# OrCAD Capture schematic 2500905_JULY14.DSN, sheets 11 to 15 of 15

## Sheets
11 PAGE5: size Custom
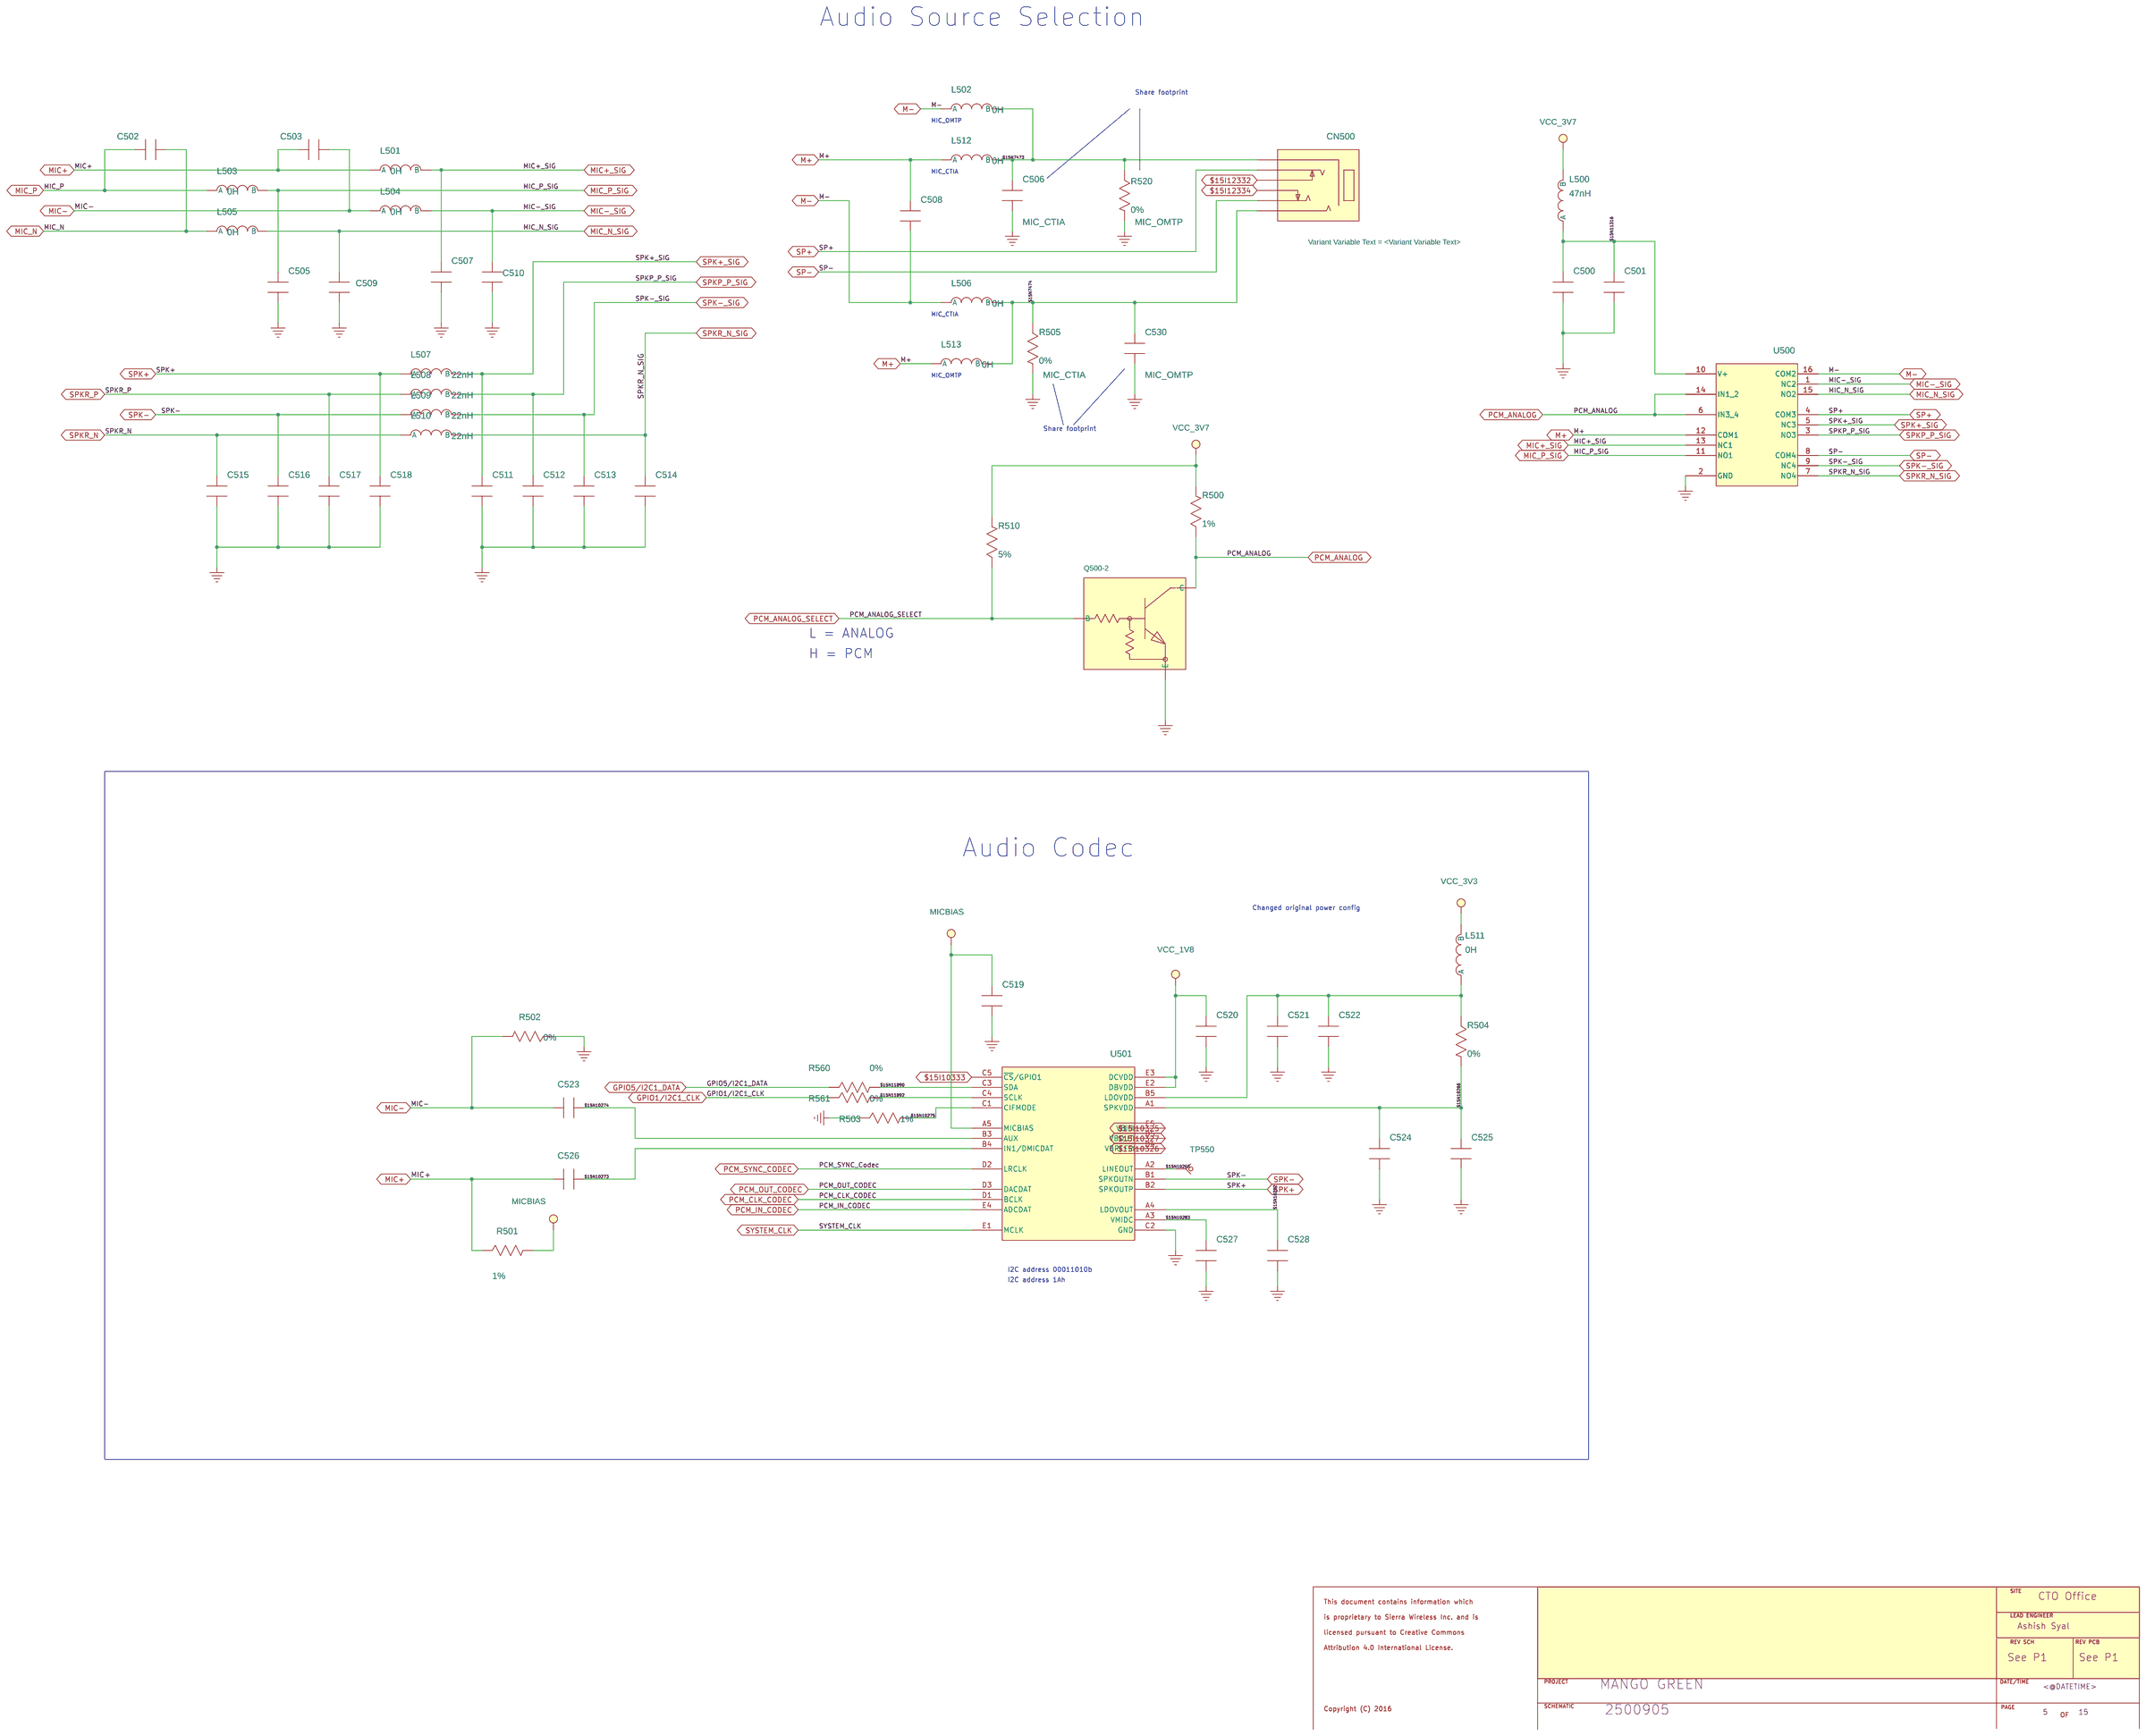
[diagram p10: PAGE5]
12 PAGE4: size Custom
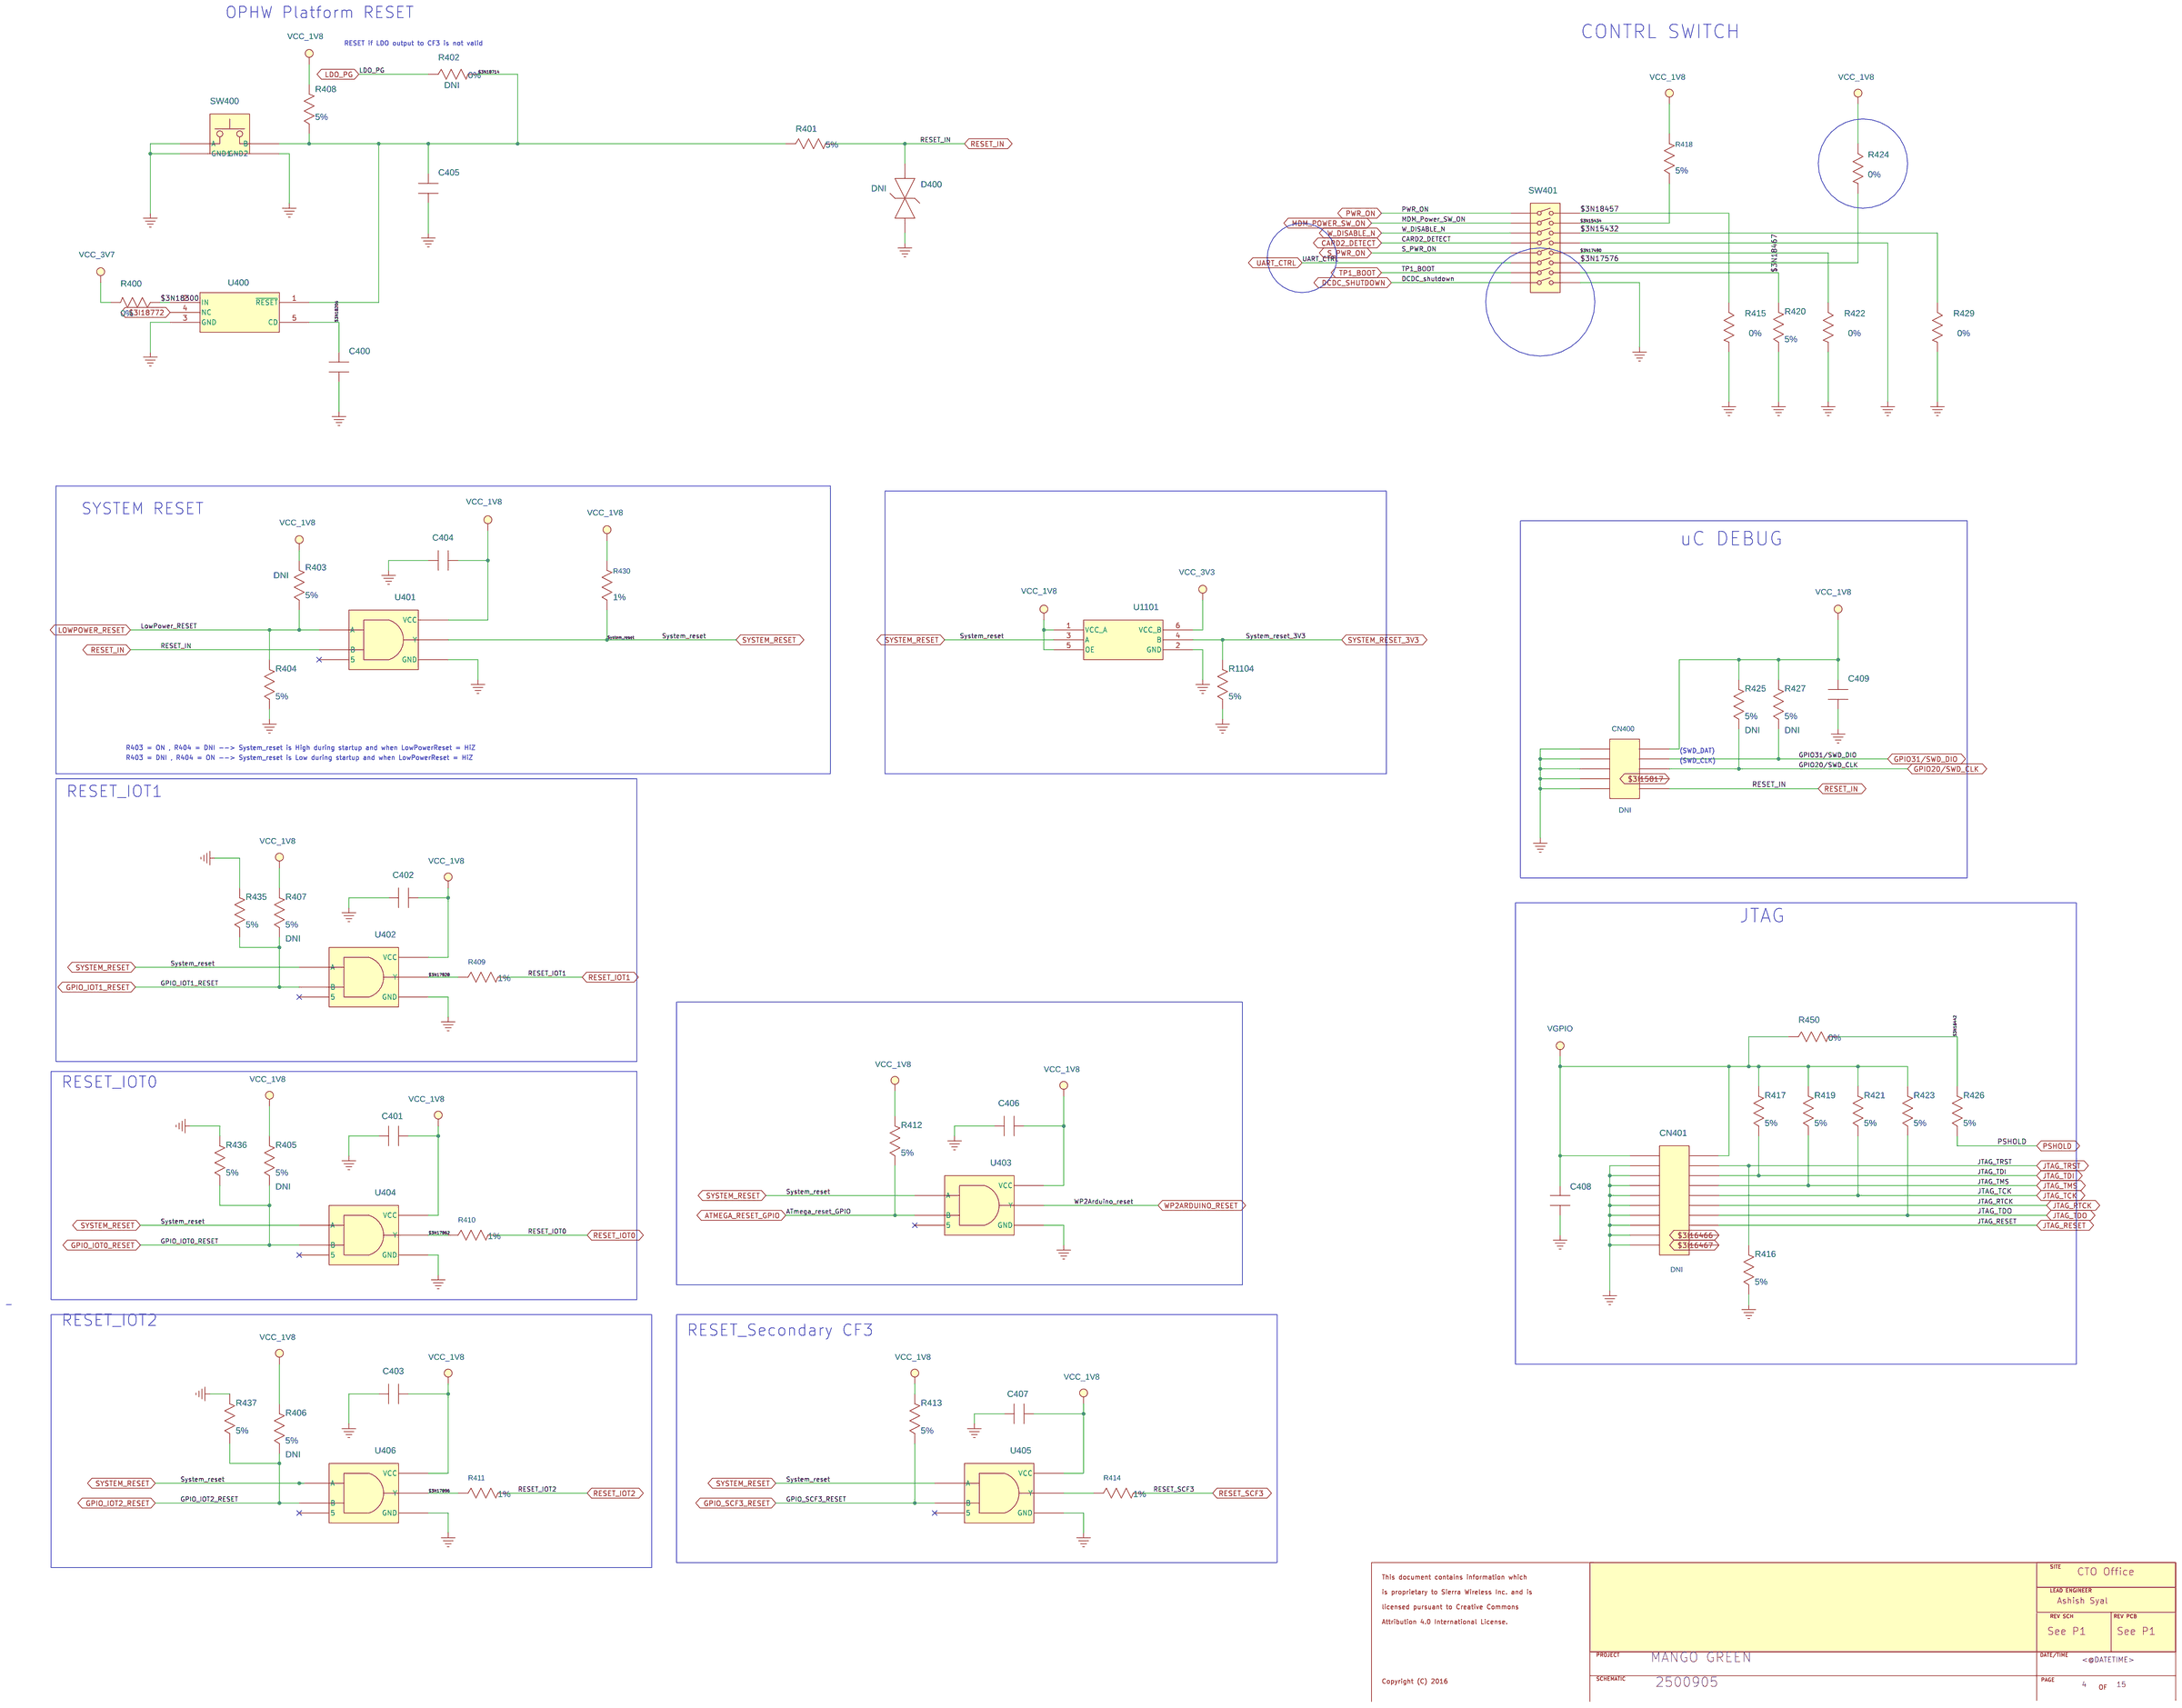
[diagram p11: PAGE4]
13 PAGE3: size Custom
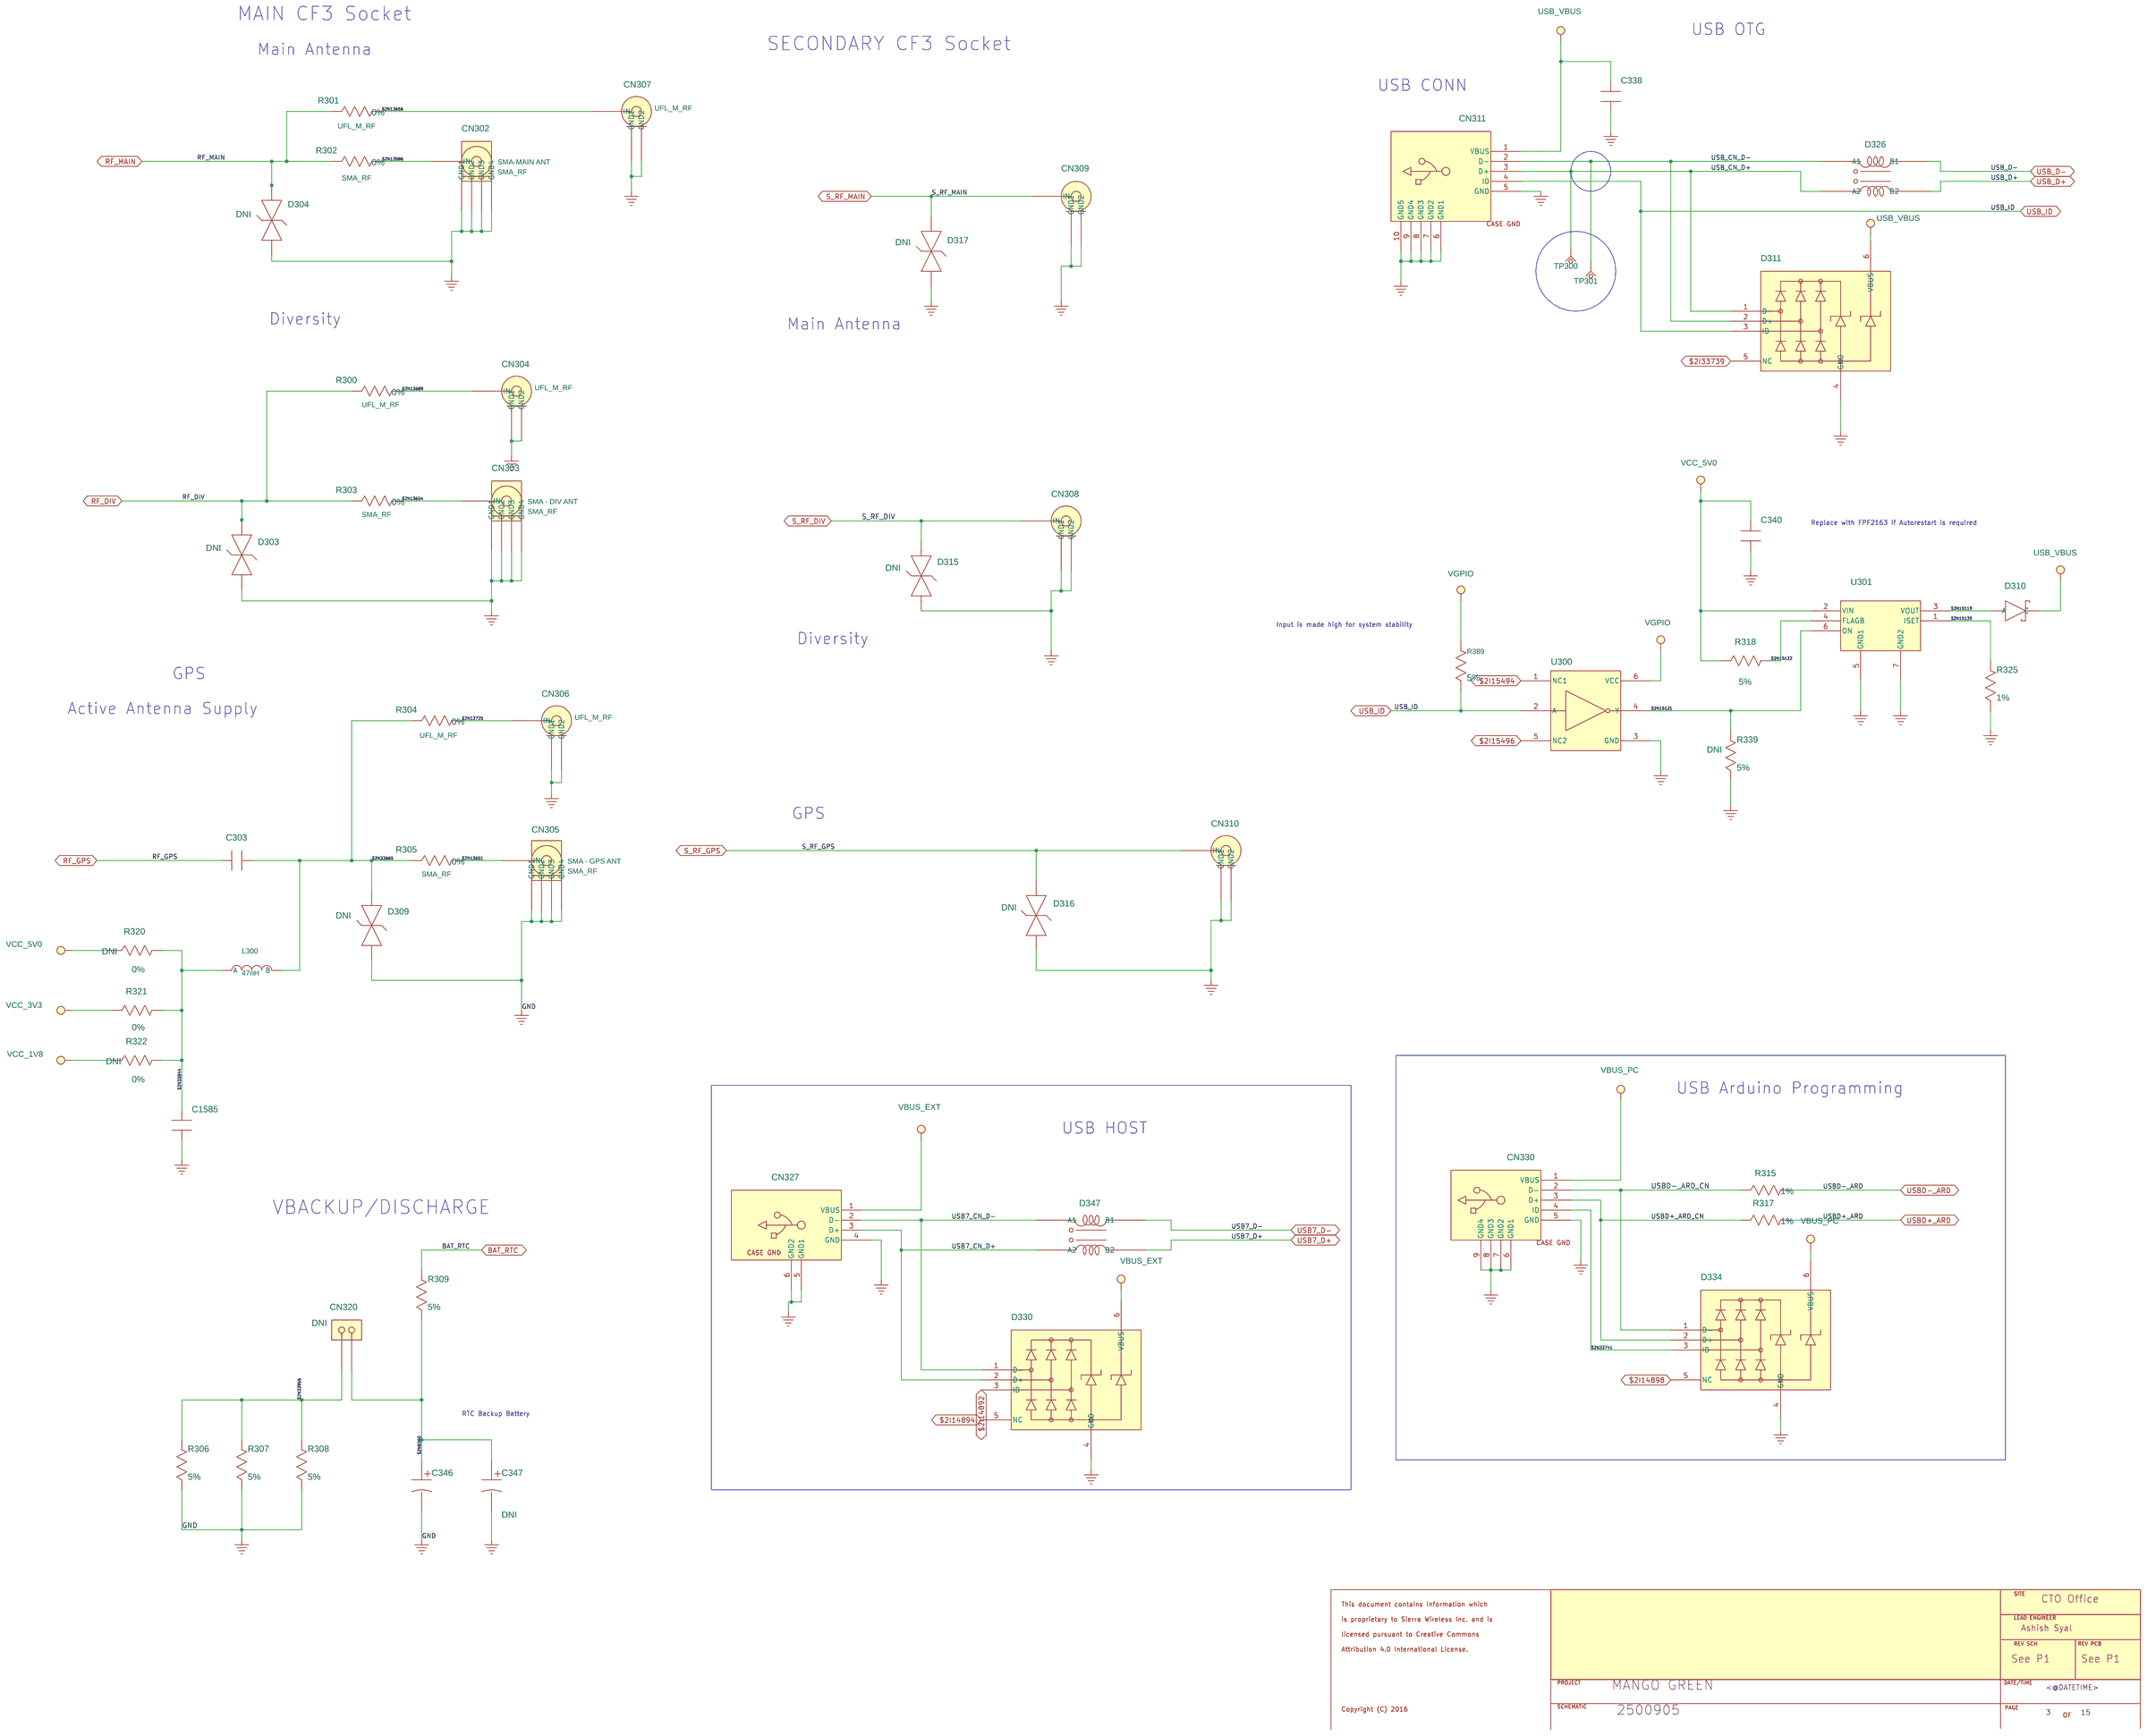
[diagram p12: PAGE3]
14 PAGE2: size Custom
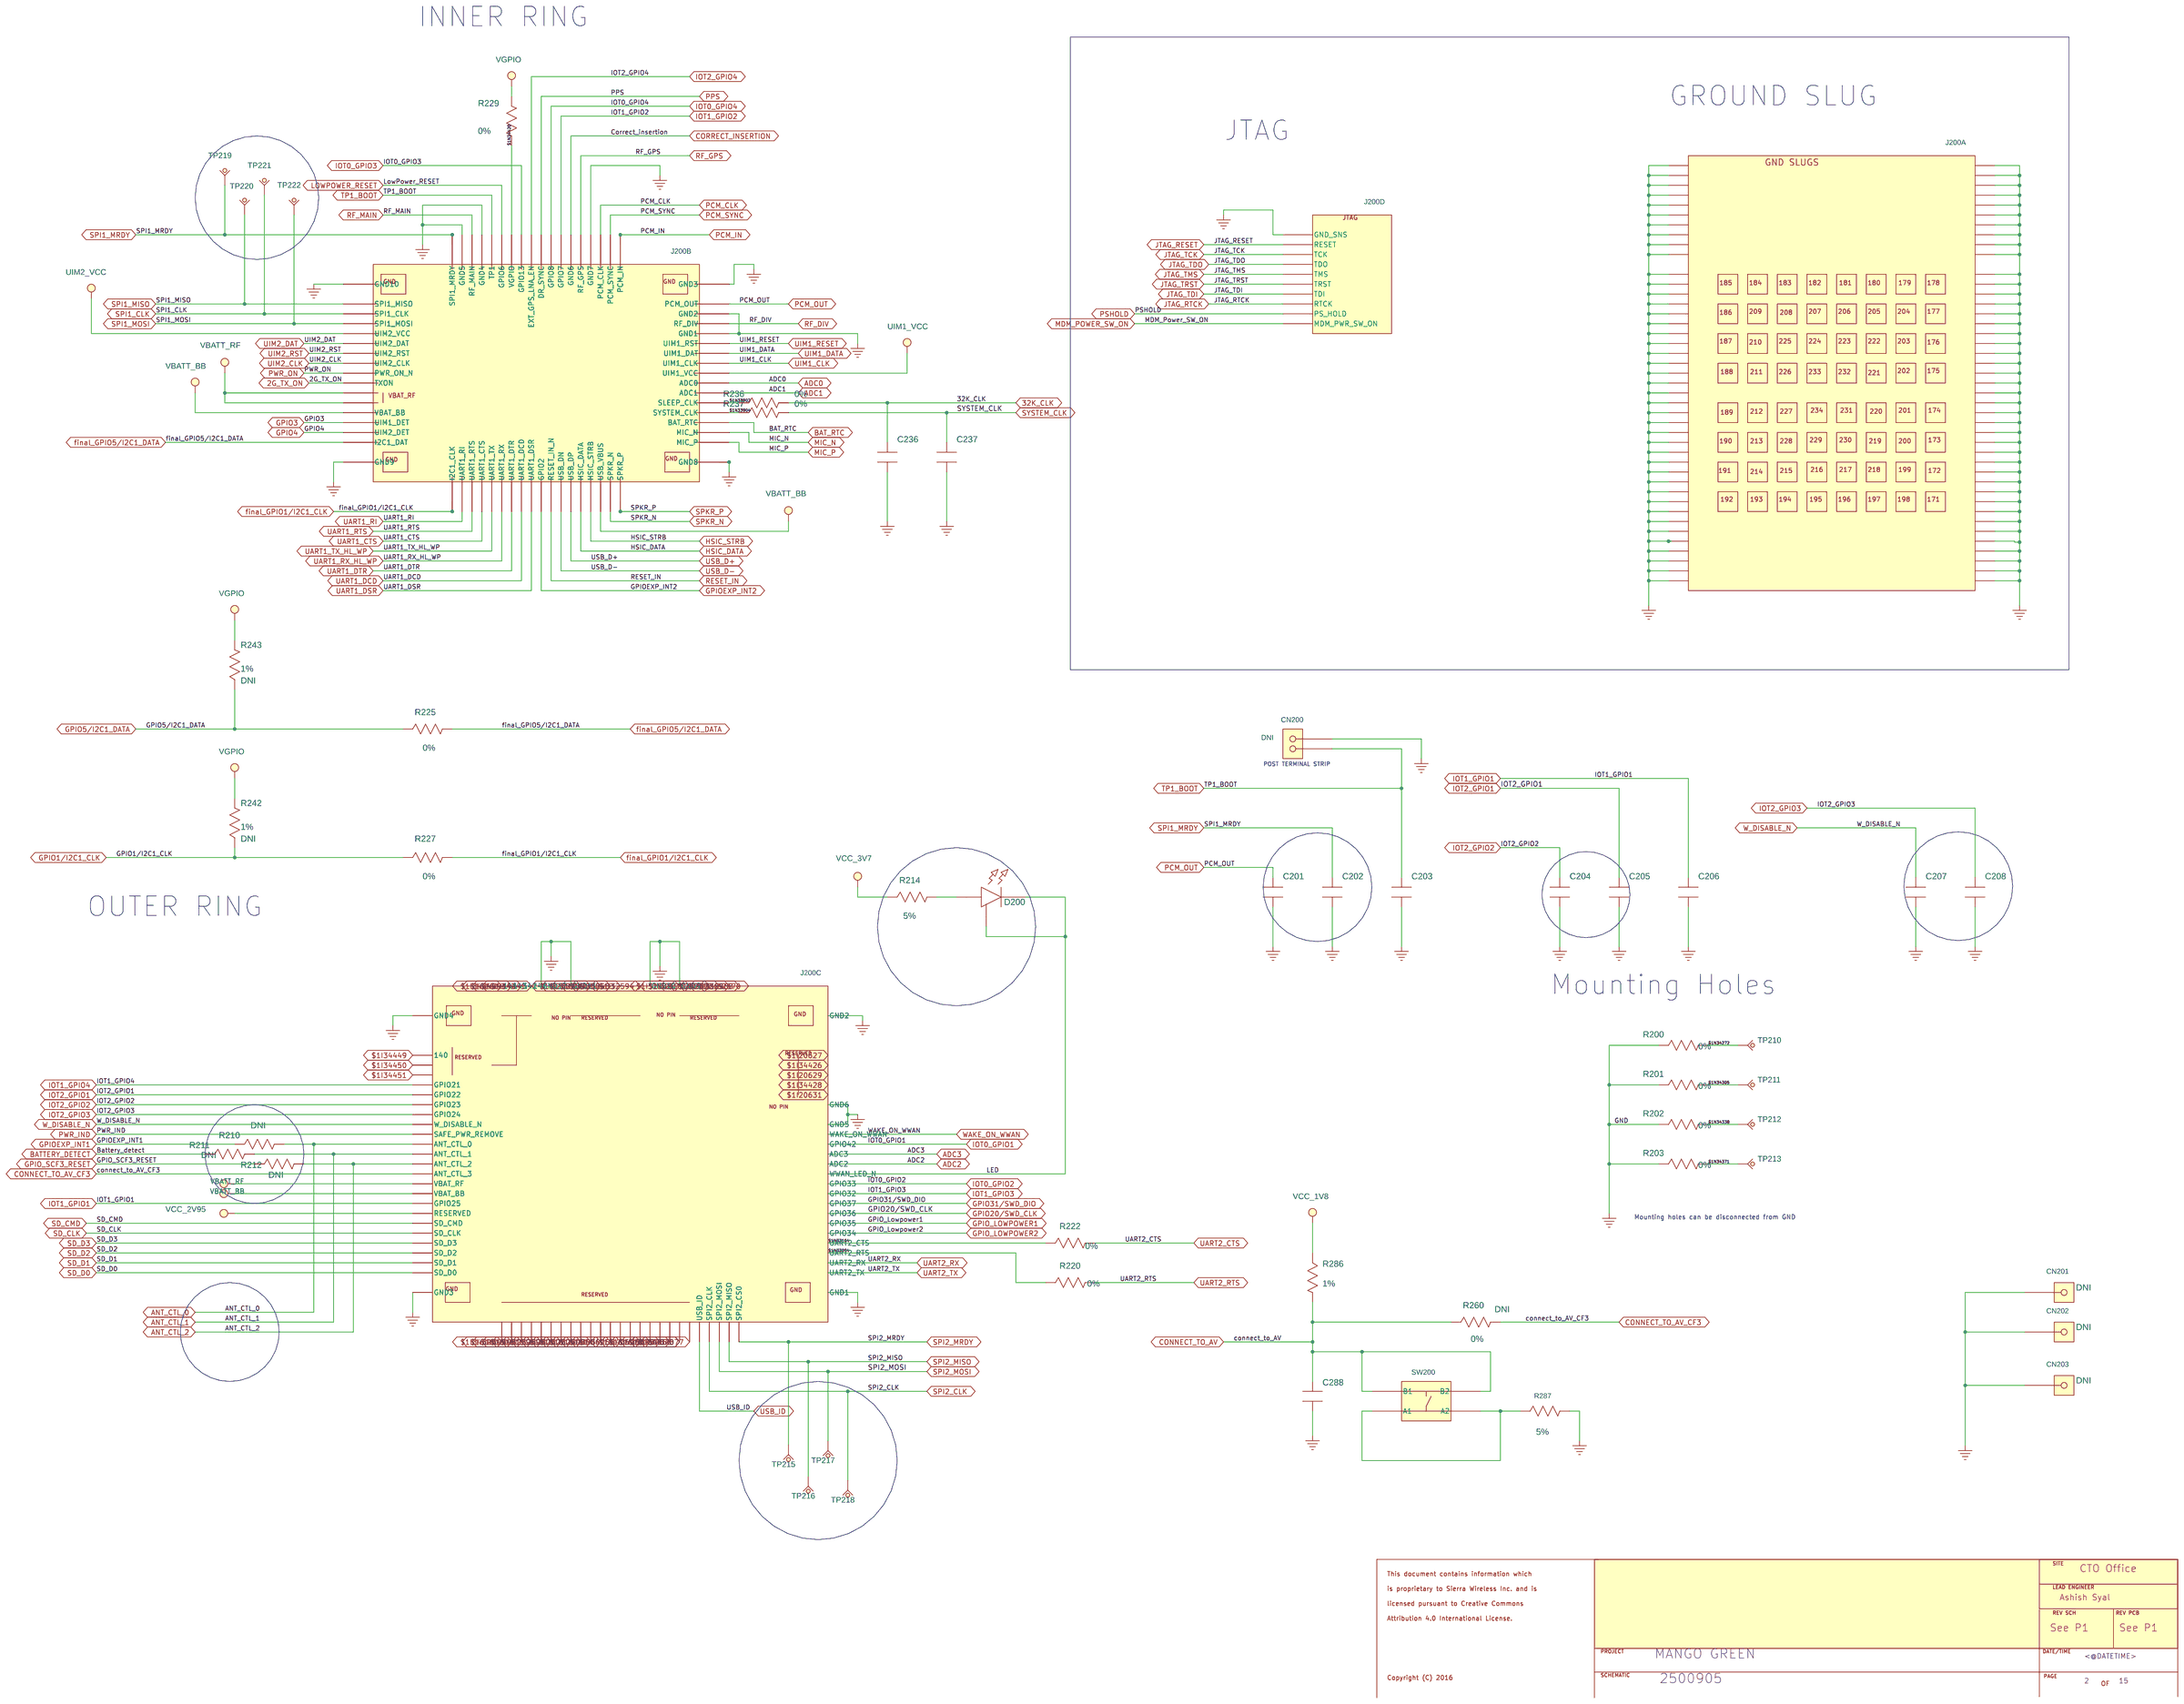
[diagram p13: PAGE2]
15 PAGE1
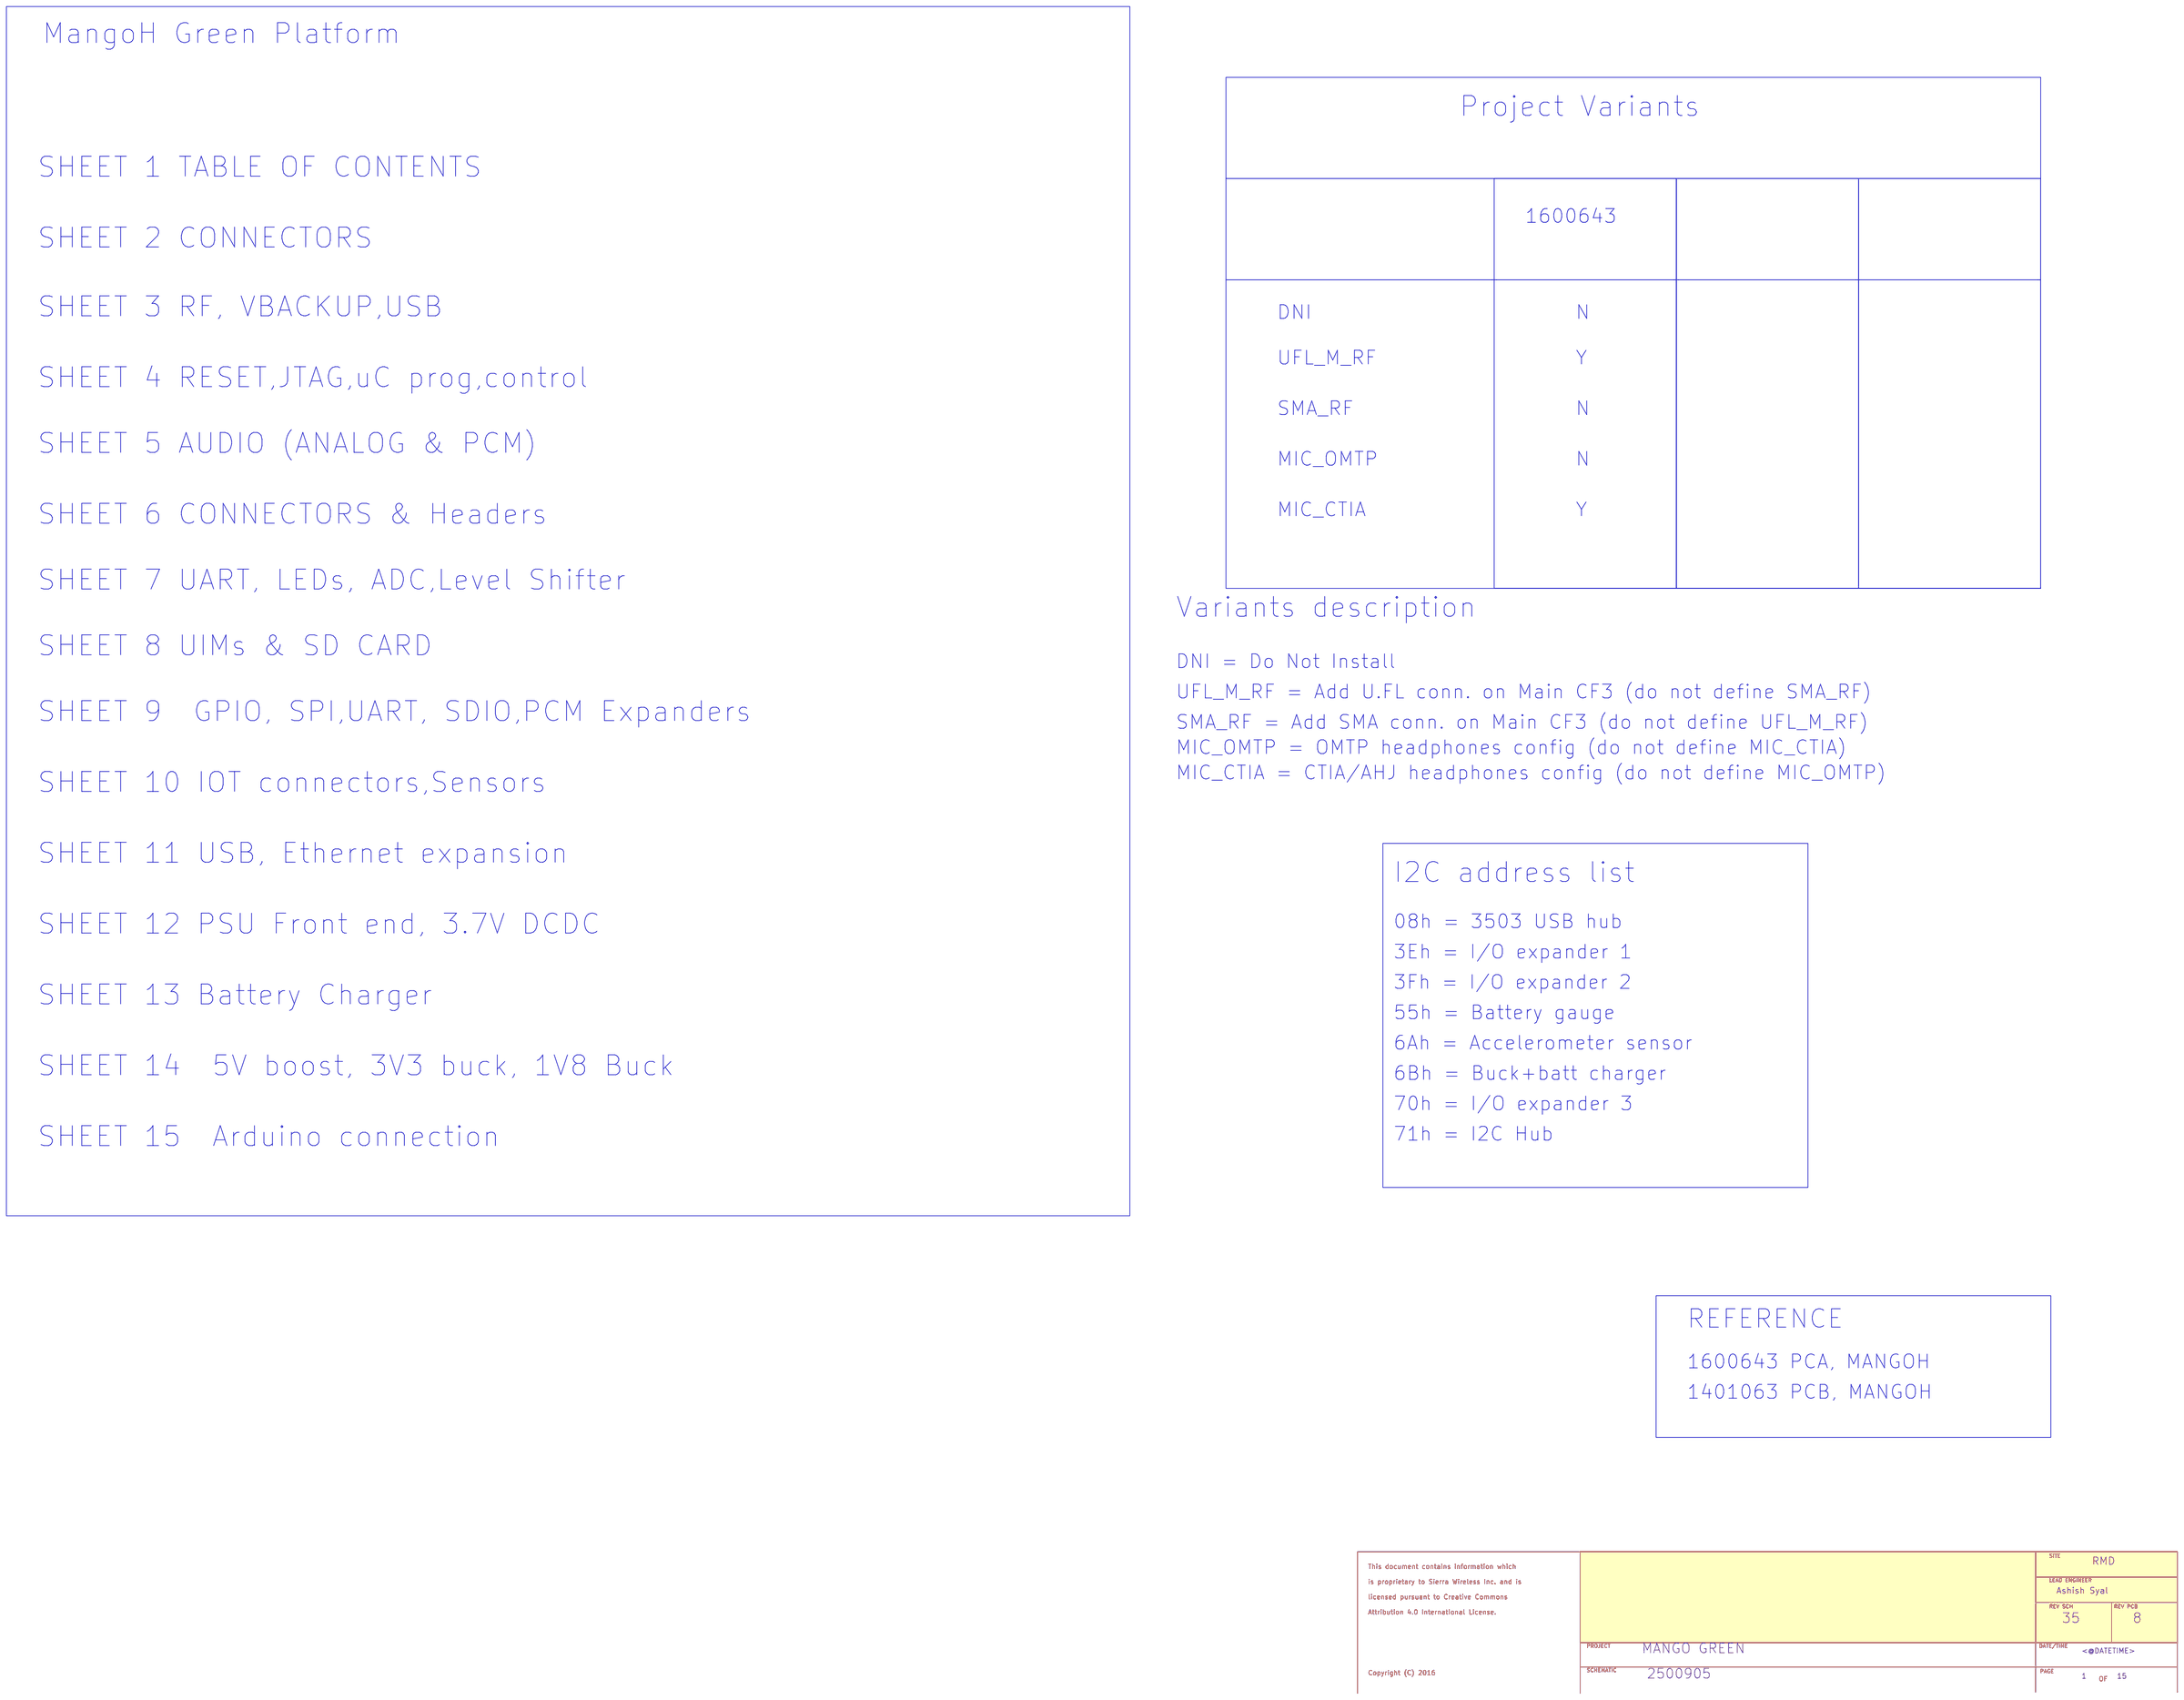
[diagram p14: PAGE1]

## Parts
sheet PAGE1
1  C_OPEN_HW  [TP]
sheet PAGE2
2  C_OPEN_HW  [TP]
C201  22pF  [0402C]
C202  22pF  [0402C]
C203  22pF  [0402C]
C204  22pF  [0402C]
C205  22pF  [0402C]
C206  22pF  [0402C]
C207  22pF  [0402C]
C208  22pF  [0402C]
C236  12pF  [0402C]
C237  12pF  [0402C]
C288  100nF  [0402C]
CN200  CN_2P_SINGLE_ROW  [CONN_2P_0508x0254_VERTICAL_HEADER_SINGLE_ROW_THRU_SAMTEC_TSW]
CN201  CN_1P_SINGLE_ROW  [TP_THRU_0235_RND_0160D]
CN202  CN_1P_SINGLE_ROW  [TP_THRU_0235_RND_0160D]
CN203  CN_1P_SINGLE_ROW  [TP_THRU_0235_RND_0160D]
D200  LED GREEN  [LED_3P_0300x0200_RA]
J200  MULTI_SYMBOL_SOCKET_LGA-244  [LGA_244P_CF3_2650x2550_SNAP_IN_SOCKET_SMK]  (sections A,B,C,D)
R200  0  [0402R]
R201  0  [0402R]
R202  0  [0402R]
R203  0  [0402R]
R210  0  [0402R]
R211  0  [0402R]
R212  0  [0402R]
R214  1.5K  [0402R]
R220  0  [0402R]
R222  0  [0402R]
R225  0  [0402R]
R227  0  [0402R]
R229  0  [0402R]
R236  0  [0402R]
R237  0  [0402R]
R242  2.2K  [0402R]
R243  2.2K  [0402R]
R260  0  [0402R]
R286  10K  [0402R]
R287  100  [0402R]
SW200  SW_4P_PTS810 SJK 250 SMTR LFS  [SW_4P_0420x0320_0215CC]
TP210  TESTPOINT_0650_RND_0350H  [TP_0650_RND_0350H_NP]
TP211  TESTPOINT_0650_RND_0350H  [TP_0650_RND_0350H_NP]
TP212  TESTPOINT_0650_RND_0350H  [TP_0650_RND_0350H_NP]
TP213  TESTPOINT_0650_RND_0350H  [TP_0650_RND_0350H_NP]
TP215  TESTPOINT_0100_RND  [TP_0100_RND_NP]
TP216  TESTPOINT_0100_RND  [TP_0100_RND_NP]
TP217  TESTPOINT_0100_RND  [TP_0100_RND_NP]
TP218  TESTPOINT_0100_RND  [TP_0100_RND_NP]
TP219  TESTPOINT_0100_RND  [TP_0100_RND_NP]
TP220  TESTPOINT_0100_RND  [TP_0100_RND_NP]
TP221  TESTPOINT_0100_RND  [TP_0100_RND_NP]
TP222  TESTPOINT_0100_RND  [TP_0100_RND_NP]
sheet PAGE3
3  C_OPEN_HW  [TP]
C303  15pF  [0402C]
C338  10uF  [0603C]
C340  10uF  [0603C]
C346  1.5mF  [CAP_2P_0720x0630_POL_NIB]
C347  1.5mF  [CAP_2P_0720x0630_POL_NIB]
C1585  22pF  [0402C]
CN302  SMA  [CONN_5P_0955x1430_RA_EDGE_MOUNT_RF_SMA]
CN303  SMA  [CONN_5P_0955x1430_RA_EDGE_MOUNT_RF_SMA]
CN304  CN_3P_RF_GENERIC  [CONN_3P_0300x0310_RF_HIROSE]
CN305  SMA  [CONN_5P_0955x1430_RA_EDGE_MOUNT_RF_SMA]
CN306  CN_3P_RF_GENERIC  [CONN_3P_0300x0310_RF_HIROSE]
CN307  CN_3P_RF_GENERIC  [CONN_3P_0300x0310_RF_HIROSE]
CN308  CN_3P_RF_GENERIC  [CONN_3P_0300x0310_RF_HIROSE]
CN309  CN_3P_RF_GENERIC  [CONN_3P_0300x0310_RF_HIROSE]
CN310  CN_3P_RF_GENERIC  [CONN_3P_0300x0310_RF_HIROSE]
CN311  CN_5P_USB_5P_GND  [CONN_5P_0750x0560_USB_5GND_HRS_ZX62RD]
CN320  POST TERMINAL STRIP  [CONN_2P_0508x0254_VERTICAL_HEADER_SINGLE_ROW_THRU_SAMTEC_TSW]
CN327  CN_4P_USB_2P_GND  [CONN_4P_1450x1400_USB_2GND_RA_THRU]
CN330  USB CONN  [CONN_5P_0770x0900_USB_4GND_SMK_CSS5005-0401]
D303  0.05pF  [0402E]
D304  0.05pF  [0402E]
D309  0.05pF  [0402E]
D310  DIODE_SCHOTTKY  [DIO_2P_0270x0165_SOD123]
D311  DIODE_6P_ESD_TPD4S012DRYR  [DFN_6P_0145x0100_0050CC]
D315  0.05pF  [0402E]
D316  0.05pF  [0402E]
D317  0.05pF  [0402E]
D326  0H  [IND_4P_0100x0125_0055CC]
D330  DIODE_6P_ESD_TPD4S012DRYR  [DFN_6P_0145x0100_0050CC]
D334  DIODE_6P_ESD_TPD4S012DRYR  [DFN_6P_0145x0100_0050CC]
D347  0H  [IND_4P_0100x0125_0055CC]
L300  47nH  [0402L]
R300  0  [0402R]
R301  0  [0402R]
R302  0  [0402R]
R303  0  [0402R]
R304  0  [0402R]
R305  0  [0402R]
R306  300  [0402R]
R307  300  [0402R]
R308  300  [0402R]
R309  10K  [0402R]
R315  22  [0402R]
R317  22  [0402R]
R318  51K  [0402R]
R320  0  [0402R]
R321  0  [0402R]
R322  0  [0402R]
R325  470  [0402R]
R339  51K  [0402R]
R389  51K  [0402R]
TP300  TESTPOINT_0100_RND  [TP_0100_RND_NP]
TP301  TESTPOINT_0100_RND  [TP_0100_RND_NP]
U300  SN74LVC1G04DRYRG4  [DFN_6P_0145x0100_0050CC]
U301  FPF2164  [DFN_6P_0200x0200_SLUG_0140x0080_0065CC]
sheet PAGE4
4  C_OPEN_HW  [TP]
C400  100nF  [0402C]
C401  100nF  [0402C]
C402  100nF  [0402C]
C403  100nF  [0402C]
C404  100nF  [0402C]
C405  100nF  [0402C]
C406  100nF  [0402C]
C407  100nF  [0402C]
C408  100nF  [0402C]
C409  100nF  [0402C]
CN400  SFMC-105-02-L-D-TR  [CONN_10P_0673x0305_0127CC_SMT]
CN401  SFMC-110-02-L-D-TR  [CONN_20P_1308x0305_0127CC_SMT]
D400  0.05pF  [0402E]
R400  0  [0402R]
R401  100  [0402R]
R402  0  [0402R]
R403  47K  [0402R]
R404  47K  [0402R]
R405  47K  [0402R]
R406  47K  [0402R]
R407  47K  [0402R]
R408  47K  [0402R]
R409  330  [0402R]
R410  330  [0402R]
R411  330  [0402R]
R412  47K  [0402R]
R413  47K  [0402R]
R414  330  [0402R]
R415  0  [0402R]
R416  10K  [0402R]
R417  10K  [0402R]
R418  10K  [0402R]
R419  10K  [0402R]
R420  10K  [0402R]
R421  10K  [0402R]
R422  0  [0402R]
R423  10K  [0402R]
R424  0  [0402R]
R425  10K  [0402R]
R426  10K  [0402R]
R427  10K  [0402R]
R429  0  [0402R]
R430  10K  [0402R]
R435  47K  [0402R]
R436  47K  [0402R]
R437  47K  [0402R]
R450  0  [0402R]
R1104  47K  [0402R]
SW400  SW_4P_T6HA-25GQB  [SW_4P_0850x0600_RT_ANGLE_SPST]
SW401  1-1571983-1  [SW_16P_1128x0620_0127CC_DIP_SPST]
U400  NCP303LSN30T1G  [SOT23_5P_0300x0160_0095CC]
U401  IC_5P_AND_GATE_2_INPUT_GENERI  [DFN_6P_0145x0100_0050CC]
U402  IC_5P_AND_GATE_2_INPUT_GENERI  [DFN_6P_0145x0100_0050CC]
U403  IC_5P_AND_GATE_2_INPUT_GENERI  [DFN_6P_0145x0100_0050CC]
U404  IC_5P_AND_GATE_2_INPUT_GENERI  [DFN_6P_0145x0100_0050CC]
U405  IC_5P_AND_GATE_2_INPUT_GENERI  [DFN_6P_0145x0100_0050CC]
U406  IC_5P_AND_GATE_2_INPUT_GENERI  [DFN_6P_0145x0100_0050CC]
U1101  IC_6P_NTB0101GW  [SC88_6P_0210x0125_0065CC]
sheet PAGE5
5  C_OPEN_HW  [TP]
C500  22pF  [0402C]
C501  100nF  [0402C]
C502  100pF  [0402C]
C503  100pF  [0402C]
C505  100pF  [0402C]
C506  100pF  [0402C]
C507  100pF  [0402C]
C508  100pF  [0402C]
C509  100pF  [0402C]
C510  100pF  [0402C]
C511  22pF  [0402C]
C512  22pF  [0402C]
C513  22pF  [0402C]
C514  22pF  [0402C]
C515  100pF  [0402C]
C516  100pF  [0402C]
C517  100pF  [0402C]
C518  100pF  [0402C]
C519  4.7uF  [0402C]
C520  4.7uF  [0402C]
C521  4.7uF  [0402C]
C522  100nF  [0402C]
C523  1uF  [0402C]
C524  100nF  [0402C]
C525  4.7uF  [0402C]
C526  1uF  [0402C]
C527  4.7uF  [0402C]
C528  2.2uF  [0603C]
C530  100pF  [0402C]
CN500  3.5MM AUDIO JACK  [CONN_6P_1480x0640_AUDIO_JACK_DUAL]
L500  47nH  [0402L]
L501  0H  [0402L]
L502  0H  [0402L]
L503  0H  [0402L]
L504  0H  [0402L]
L505  0H  [0402L]
L506  0H  [0402L]
L507  22nH  [0402L]
L508  22nH  [0402L]
L509  22nH  [0402L]
L510  22nH  [0402L]
L511  0H  [0603L]
L512  0H  [0402L]
L513  0H  [0402L]
Q500  NSBC114YDP6T5G  [SOT963_6P_0100x0080_0035CC]  (section -2)
R500  1K  [0402R]
R501  2.2K  [0402R]
R502  0  [0402R]
R503  20K  [0402R]
R504  0  [0402R]
R505  0  [0402R]
R510  10K  [0402R]
R520  0  [0402R]
R560  0  [0402R]
R561  0  [0402R]
TP550  TESTPOINT_0035_RND  [TP_0035_RND_NP]
U500  TS3A44159RSVR  [QFN_16P_0260x0180_0040CC]
U501  WM8944BECS/R  [BGA_25P_0241x0241_0050CC_0030PD]

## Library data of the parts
1 = Sierra_Title_Block_0: @DATETIME: <@DATETIME>; @Name: 2500905; @SheetTotal: 15; AUTHOR: Ashish Syal; PROJECT: MANGO GREEN; REVISION_PCB: 8; REVISION_SCH: 35; SITE: RMD
2-5 = Sierra_Title_Block_0: @DATETIME: <@DATETIME>; @Name: 2500905; @SheetTotal: 15; AUTHOR: Ashish Syal; PROJECT: MANGO GREEN; REVISION_PCB: See P1; REVISION_SCH: See P1; SITE: CTO Office
C201-C208 C500 C511-C514 C1585 = CAP_GRM1555C1H220JA01D: ASSEMBLY: <ASSEMBLY>; Variant Variable Text: <Variant Variable Text>
C236 C237 = CAP_GRM1555C1H120JA01D: ASSEMBLY: <ASSEMBLY>; Variant Variable Text: <Variant Variable Text>
C288 C400-C409 C501 C522 C524 = CAP_NMC0402X7R104K16TRPF: ASSEMBLY: <ASSEMBLY>; Variant Variable Text: <Variant Variable Text>
CN200 CN320 = CN_2P_SINGLE_ROW: ASSEMBLY: <ASSEMBLY>; Variant Variable Text: DNI
CN201-CN203 = CN_1P_SINGLE_ROW: ASSEMBLY: <ASSEMBLY>; Variant Variable Text: DNI
D200 = LED_3P: ASSEMBLY: <ASSEMBLY>; Variant Variable Text: <Variant Variable Text>
J200 = MULTI_SYMBOL_SOCKET_LGA-244_0: ASSEMBLY: <ASSEMBLY>; Variant Variable Text: <Variant Variable Text>
R200-R203 R220 R222 R225 R227 R229 R236 R237 R321 R400 R415 R422 R424 R429 R450 R502 R504 R560 R561 = RES_RK73Z1ETTP: ASSEMBLY: <ASSEMBLY>; TOLERANCE: 0%; Variant Variable Text: <Variant Variable Text>
R210-R212 = RES_RK73Z1ETTP: ASSEMBLY: <ASSEMBLY>; TOLERANCE: <TOLERANCE>; Variant Variable Text: DNI
R214 = RES_RK73B1ETTP152J: ASSEMBLY: <ASSEMBLY>; TOLERANCE: 5%; Variant Variable Text: <Variant Variable Text>
R242 R243 = RES_RK73H1ETTP2201F: ASSEMBLY: <ASSEMBLY>; TOLERANCE: 1%; Variant Variable Text: DNI
R260 R320 R322 R402 = RES_RK73Z1ETTP: ASSEMBLY: <ASSEMBLY>; TOLERANCE: 0%; Variant Variable Text: DNI
R286 R430 = RES_MCR01MZPF1002: ASSEMBLY: <ASSEMBLY>; TOLERANCE: 1%; Variant Variable Text: <Variant Variable Text>
R287 R401 = RES_RK73B1ETTP101J_0: ASSEMBLY: <ASSEMBLY>; TOLERANCE: 5%; Variant Variable Text: <Variant Variable Text>
SW200 = SW_4P_PTS810_SJK_250_SMTR_LFS: ASSEMBLY: <ASSEMBLY>; Variant Variable Text: <Variant Variable Text>
TP210-TP213 = TESTPOINT: TEST POINT, ROUND, 6.5mm DIAMETER, 3.5mm DIAMETER HOLE; CATEGORY: Layout Feature; DXDB_LIBNAME: Layout_Feature; OWNER: Chris Ivanciuc; Part Height: 0.01mm; REQUESTOR: Chris Ivanciuc
TP215-TP222 TP300 TP301 = TESTPOINT: TEST POINT, ROUND, 1mm DIAMETER; CATEGORY: Layout Feature; DXDB_LIBNAME: Layout_Feature; OWNER: Michael Sorensen; Part Height: 0.01mm; REQUESTOR: Michael Sorensen
C303 = CAP_GRM1555C1H150JA01D: ASSEMBLY: <ASSEMBLY>; Variant Variable Text: <Variant Variable Text>
C338 C340 = CAP_GRM188R61A106ME69D: ASSEMBLY: <ASSEMBLY>; Variant Variable Text: <Variant Variable Text>
C346 = CAP_POL-592D158X06R3R2T20H: ASSEMBLY: <ASSEMBLY>; Variant Variable Text: <Variant Variable Text>
C347 = CAP_POL-592D158X06R3R2T20H: ASSEMBLY: <ASSEMBLY>; Variant Variable Text: DNI
CN302 = CN_5P_RF_GENERIC: ASSEMBLY: SMA-MAIN ANT; Variant Variable Text: SMA_RF
CN303 = CN_5P_RF_GENERIC: ASSEMBLY: SMA - DIV ANT; Variant Variable Text: SMA_RF
CN304 CN306 CN307 = CN_3P_RF_GENERIC: ASSEMBLY: <ASSEMBLY>; Variant Variable Text: UFL_M_RF
CN305 = CN_5P_RF_GENERIC: ASSEMBLY: SMA - GPS ANT; Variant Variable Text: SMA_RF
CN308-CN310 = CN_3P_RF_GENERIC: ASSEMBLY: <ASSEMBLY>
CN311 = CN_5P_USB_5P_GND_0: ASSEMBLY: <ASSEMBLY>; Variant Variable Text: <Variant Variable Text>
CN327 = CN_4P_USB_2P_GND: ASSEMBLY: <ASSEMBLY>; Variant Variable Text: <Variant Variable Text>
CN330 = CN_5P_USB_4P_GND: ASSEMBLY: <ASSEMBLY>; Variant Variable Text: <Variant Variable Text>
D303 D304 D309 D315-D317 D400 = DIODE_ESD_SUPPRESSOR_0: ASSEMBLY: <ASSEMBLY>; Variant Variable Text: DNI
D310 = DIODE_SCHOTTKY_0: ASSEMBLY: <ASSEMBLY>; Variant Variable Text: <Variant Variable Text>
D311 D330 D334 = DIODE_6P_ESD_TPD4S012DRYR: ASSEMBLY: <ASSEMBLY>; Variant Variable Text: <Variant Variable Text>
D326 D347 = CHOKE_4P_COMMON_MODE_GENERIC: ASSEMBLY: <ASSEMBLY>; Variant Variable Text: <Variant Variable Text>
L300 L500 = IND_LQG15HN47NJ02D_0
R300 R301 R304 = RES_RK73Z1ETTP: ASSEMBLY: <ASSEMBLY>; TOLERANCE: 0%; Variant Variable Text: UFL_M_RF
R302 R303 R305 = RES_RK73Z1ETTP: ASSEMBLY: <ASSEMBLY>; TOLERANCE: 0%; Variant Variable Text: SMA_RF
R306-R308 = RES_RK73B1ETTP301J: ASSEMBLY: <ASSEMBLY>; TOLERANCE: 5%; Variant Variable Text: <Variant Variable Text>
R309 R416-R421 R423 R426 R510 = RES_MCR01MZPJ103: ASSEMBLY: <ASSEMBLY>; TOLERANCE: 5%; Variant Variable Text: <Variant Variable Text>
R315 R317 = RES_RK73H1ETTP22R0F: ASSEMBLY: <ASSEMBLY>; TOLERANCE: 1%; Variant Variable Text: <Variant Variable Text>
R318 R389 = RES_MCR01MZPJ513: ASSEMBLY: <ASSEMBLY>; TOLERANCE: 5%; Variant Variable Text: <Variant Variable Text>
R325 = RES_MCR01MZPF4700: ASSEMBLY: <ASSEMBLY>; TOLERANCE: 1%; Variant Variable Text: <Variant Variable Text>
R339 = RES_MCR01MZPJ513: ASSEMBLY: <ASSEMBLY>; TOLERANCE: 5%; Variant Variable Text: DNI
U300 = IC_6P_INVERTER_GENERIC: ASSEMBLY: <ASSEMBLY>; Variant Variable Text: <Variant Variable Text>
U301 = IC_6P_LOAD_SWITCH_FPF2164: ASSEMBLY: <ASSEMBLY>; Variant Variable Text: <Variant Variable Text>
CN400 = CN_10P_DUAL_ROW_Z_NO_BUBBLES: ASSEMBLY: <ASSEMBLY>; Variant Variable Text: DNI
CN401 = CN_20P_DUAL_ROW_Z_NO_BUBBLES: ASSEMBLY: <ASSEMBLY>; Variant Variable Text: DNI
R403 R405-R407 = RES_MCR01MZPJ473: ASSEMBLY: <ASSEMBLY>; TOLERANCE: 5%; Variant Variable Text: DNI
R404 R408 R412 R413 R435-R437 R1104 = RES_MCR01MZPJ473: ASSEMBLY: <ASSEMBLY>; TOLERANCE: 5%; Variant Variable Text: <Variant Variable Text>
R409-R411 R414 = RES_RK73H1ETTP3300F: ASSEMBLY: <ASSEMBLY>; TOLERANCE: 1%; Variant Variable Text: <Variant Variable Text>
R425 R427 = RES_MCR01MZPJ103: ASSEMBLY: <ASSEMBLY>; TOLERANCE: 5%; Variant Variable Text: DNI
SW400 = SW_4P_T6HA-25GQB: ASSEMBLY: <ASSEMBLY>; Variant Variable Text: <Variant Variable Text>
SW401 = SW_16P_SPST_8POS: ASSEMBLY: <ASSEMBLY>; Variant Variable Text: <Variant Variable Text>
U400 = IC_5P_NCP303LSN30T1G: ASSEMBLY: <ASSEMBLY>; Variant Variable Text: <Variant Variable Text>
U401-U406 = IC_5P_AND_GATE_2_INPUT_GENERI_4: ASSEMBLY: <ASSEMBLY>; Variant Variable Text: <Variant Variable Text>
U1101 = IC_6P_NTB0101GW: ASSEMBLY: <ASSEMBLY>; Variant Variable Text: <Variant Variable Text>
C502 C503 C505 C507-C510 C515-C518 = CAP_GRM1555C1H101JA01D: ASSEMBLY: <ASSEMBLY>; Variant Variable Text: <Variant Variable Text>
C506 = CAP_GRM1555C1H101JA01D: ASSEMBLY: <ASSEMBLY>; Variant Variable Text: MIC_CTIA
C519-C521 C525 C527 = CAP_ECJ-0EB0J475M: ASSEMBLY: <ASSEMBLY>; Variant Variable Text: <Variant Variable Text>
C523 C526 = CAP_GRM155R61A105KE15D: ASSEMBLY: <ASSEMBLY>; Variant Variable Text: <Variant Variable Text>
C528 = CAP_CE_JMK107BJ225KA-T: ASSEMBLY: <ASSEMBLY>; Variant Variable Text: <Variant Variable Text>
C530 = CAP_GRM1555C1H101JA01D: ASSEMBLY: <ASSEMBLY>; Variant Variable Text: MIC_OMTP
CN500 = CN_6P_AUDIO_JACK: ASSEMBLY: <ASSEMBLY>; Variant Variable Text: <Variant Variable Text>
L501-L506 L512 L513 = IND_BLM15AX601SN1D
L507-L510 = IND_LG_HK_1005_22NJ-T_0
L511 = IND_MPZ1608S221AT
Q500 = NPN_2RES: ASSEMBLY: <ASSEMBLY>; Variant Variable Text: <Variant Variable Text>
R500 = RES_RK73H1ETTP1001F: ASSEMBLY: <ASSEMBLY>; TOLERANCE: 1%; Variant Variable Text: <Variant Variable Text>
R501 = RES_RK73H1ETTP2201F: ASSEMBLY: <ASSEMBLY>; TOLERANCE: 1%; Variant Variable Text: <Variant Variable Text>
R503 = RES_RK73H1ETTP2002F: ASSEMBLY: <ASSEMBLY>; TOLERANCE: 1%; Variant Variable Text: <Variant Variable Text>
R505 = RES_RK73Z1ETTP: ASSEMBLY: <ASSEMBLY>; TOLERANCE: 0%; Variant Variable Text: MIC_CTIA
R520 = RES_RK73Z1ETTP: ASSEMBLY: <ASSEMBLY>; TOLERANCE: 0%; Variant Variable Text: MIC_OMTP
TP550 = TESTPOINT: TEST POINT, ROUND, 0.35mm DIAMETER; CATEGORY: Layout Feature; DXDB_LIBNAME: Layout_Feature; OWNER: Michael Sorensen; Part Height: 0.01mm; REQUESTOR: Michael Sorensen
U500 = IC_16P_TS3A44159RSVR: ASSEMBLY: <ASSEMBLY>; Variant Variable Text: <Variant Variable Text>
U501 = IC_25P_WM8944BECS_R: ASSEMBLY: <ASSEMBLY>; Variant Variable Text: <Variant Variable Text>

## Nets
GND: C201.1(A) C202.1(A) C203.1(A) C204.1(A) C205.1(A) C206.1(A) C207.1(A) C208.1(A) C236.1(A) C237.1(A) C288.1(A) C338.1(A) C340.1(A) C346.2(B) C347.2(B) C400.1(A) C401.1(A) C402.1(A) C403.1(A) C404.1(A) C405.1(A) C406.1(A) C407.1(A) C408.2(B) C409.2(B) C500.1(A) C501.1(A) C505.2(B) C506.1(A) C507.2(B) C509.1(A) C510.1(A) C511.2(B) C512.2(B) C513.2(B) C514.2(B) C515.1(A) C516.1(A) C517.1(A) C518.1(A) C519.1(A) C520.1(A) C521.1(A) C522.1(A) C524.1(A) C525.1(A) C527.1(A) C528.1(A) C530.1(A) C1585.1(A) CN200.1 CN201.1 CN202.1 CN203.1 CN302.2(GND1) CN302.3(GND2) CN302.4(GND3) CN302.5(GND4) CN303.2(GND1) CN303.3(GND2) CN303.4(GND3) CN303.5(GND4) CN304.2(GND1) CN304.3(GND2) CN305.2(GND1) CN305.3(GND2) CN305.4(GND3) CN305.5(GND4) CN306.2(GND1) CN306.3(GND2) CN307.2(GND1) CN307.3(GND2) CN308.2(GND1) CN308.3(GND2) CN309.2(GND1) CN309.3(GND2) CN310.2(GND1) CN310.3(GND2) CN311.5(GND) CN311.6(GND1) CN311.7(GND2) CN311.8(GND3) CN311.9(GND4) CN311.10(GND5) CN327.4(GND) CN327.5(GND1) CN327.6(GND2) CN330.5(GND) CN330.6(GND1) CN330.7(GND2) CN330.8(GND3) CN330.9(GND4) CN400.2 CN400.4 CN400.6 CN400.8 CN400.10 CN401.4 CN401.6 CN401.8 CN401.10 CN401.12 CN401.14 CN401.16 CN401.18 CN401.20 D303.1 D304.1 D309.1 D311.4(GND) D315.1 D316.1 D317.1 D330.4(GND) D334.4(GND) D400.1 J200.30(GND1) J200.32(GND2) J200.37(GND7) J200.48(GND4) J200.50(GND5) J200.67(GND9) J200.68(GND8) J200.69(GND3) J200.70(GND10) J200.111(GND5) J200.113(GND6) J200.125(GND9) J200.128(GND10) J200.136(GND11) J200.139(GND12) J200.167(GND3) J200.168(GND1) J200.169(GND2) J200.170(GND4) J200.171 J200.172 J200.173 J200.174 J200.175 J200.176 J200.177 J200.178 J200.179 J200.180 J200.181 J200.182 J200.183 J200.184 J200.185 J200.186 J200.187 J200.188 J200.189 J200.190 J200.191 J200.192 J200.193 J200.194 J200.195 J200.196 J200.197 J200.198 J200.199 J200.200 J200.201 J200.202 J200.203 J200.204 J200.205 J200.206 J200.207 J200.208 J200.209 J200.210 J200.211 J200.212 J200.213 J200.214 J200.215 J200.216 J200.217 J200.218 J200.219 J200.220 J200.221 J200.222 J200.223 J200.224 J200.225 J200.226 J200.227 J200.228 J200.229 J200.230 J200.231 J200.232 J200.233 J200.234 J200.235(GND_SNS) J200.G1 J200.G2 J200.G3 J200.G4 J200.G5 J200.G6 J200.G7 J200.G8 J200.G9 J200.G10 J200.G11 J200.G12 J200.G13 J200.G14 J200.G15 J200.G16 J200.G17 J200.G18 J200.G19 J200.G20 Q500.4(E) R200.1(A) R201.1(A) R202.1(A) R203.1(A) R287.2(B) R306.1(A) R307.1(A) R308.1(A) R325.1(A) R339.1(A) R404.1(A) R415.2(B) R416.1(A) R420.1(A) R422.2(B) R429.2(B) R435.2(B) R436.2(B) R437.2(B) R502.1(A) R503.1(A) R505.2(B) R520.2(B) R1104.1(A) SW400.1(A) SW400.3(GND1) SW400.4(GND2) SW401.9 SW401.13 U300.3(GND) U301.5(GND1) U301.7(GND2) U400.3(GND) U401.3(GND) U402.3(GND) U403.3(GND) U404.3(GND) U405.3(GND) U406.3(GND) U500.2(GND) U501.C2(GND) U1101.2(GND) ; also on sheet 1 2 3 4 5 6 7 8 9 10
VBATT_BB: J200.16(USB_VBUS) J200.63(VBAT_BB) J200.158(VBAT_BB) ; also on sheet 2
VBATT_RF: J200.61 J200.62 J200.157(VBAT_RF) ; also on sheet 2
VBUS_EXT: CN327.1(VBUS) D330.6(VBUS) ; also on sheet 5
VBUS_PC: CN330.1(VBUS) D334.6(VBUS)
VCC_1V8: C401.2(B) C402.2(B) C403.2(B) C404.2(B) C406.2(B) C407.2(B) C409.1(A) C520.2(B) CN400.1 R286.1(A) R322.1(A) R403.2(B) R405.2(B) R406.2(B) R407.2(B) R408.2(B) R412.2(B) R413.2(B) R418.2(B) R424.1(A) R425.2(B) R427.2(B) R430.2(B) U401.6(VCC) U402.6(VCC) U403.6(VCC) U404.6(VCC) U405.6(VCC) U406.6(VCC) U501.E2(DBVDD) U501.E3(DCVDD) U1101.1(VCC_A) U1101.5(OE) ; also on sheet 1 3 5 6 7 8 9 10
VCC_2V95: J200.160(RESERVED) ; also on sheet 7 8
VCC_3V3: L511.2(B) R321.1(A) U1101.6(VCC_B) ; also on sheet 1 3 5 6 7 8
VCC_3V7: L500.2(B) R214.1(A) R400.2(B) R500.2(B) R510.2(B) ; also on sheet 2 3 4 8 9 10
VCC_5V0: C340.2(B) R318.1(A) R320.1(A) U301.2(VIN) ; also on sheet 1 3 5
2G_TX_ON: J200.60(TXON) ; also on sheet 9 10
32K_CLK: C236.2(B) R236.2(B) ; also on sheet 10
$1I20627: J200.118
$1I20629: J200.116
$1I20631: J200.114
$1I32568: J200.119
$1I32569: J200.120
$1I32570: J200.123
$1I32571: J200.124
$1I32572: J200.121
$1I32573: J200.122
$1I32582: J200.130
$1I32583: J200.131
$1I32584: J200.132
$1I32585: J200.133
$1I32586: J200.134
$1I32587: J200.135
$1I32594: J200.129
$1I32596: J200.75
$1I32598: J200.76
$1I32600: J200.77
$1I32602: J200.78
$1I32604: J200.79
$1I32606: J200.80
$1I34063: J200.86
$1I34064: J200.85
$1I34065: J200.84
$1I34066: J200.83
$1I34067: J200.82
$1I34068: J200.81
$1I34075: J200.87
$1I34076: J200.88
$1I34077: J200.90
$1I34078: J200.89
$1I34426: J200.117
$1I34428: J200.115
$1I34441: J200.140(141)
$1I34442: J200.141(142)
$1I34443: J200.142(143)
$1I34444: J200.143(144)
$1I34449: J200.144(140)
$1I34450: J200.145
$1I34451: J200.146
$1I34517: J200.74
$1I34518: J200.73
$1I34519: J200.72
$1I34520: J200.71
$2I14892: D330.3(ID)
$2I14894: D330.5(NC)
$2I14898: D334.5(NC)
$2I15494: U300.1(NC1)
$2I15496: U300.5(NC2)
$2I33739: D311.5(NC)
$3I15817: CN400.7
$3I16466: CN401.17
$3I16467: CN401.19
$3I18772: U400.4(NC)
$15I10325: U501.E5(VBIN)
$15I10326: U501.D4(VBREFR)
$15I10327: U501.D5(VBOUT)
$15I10333: U501.C5(~{CS}/GPIO1)
$15I12332: CN500.3
$15I12334: CN500.2
ADC0: J200.25(ADC0) ; also on sheet 6
ADC1: J200.24(ADC1) ; also on sheet 6
ADC2: J200.107(ADC2) ; also on sheet 6
ADC3: J200.108(ADC3) ; also on sheet 6
ANT_CTL_0: J200.153(ANT_CTL_0) R210.2(B) ; also on sheet 10
ANT_CTL_1: J200.154(ANT_CTL_1) R211.2(B) ; also on sheet 10
ANT_CTL_2: J200.155(ANT_CTL_2) R212.2(B) ; also on sheet 10
ATMEGA_RESET_GPIO: R412.1(A) U403.2(B) ; also on sheet 7
BAT_RTC: J200.21(BAT_RTC) R309.2(B)
BATTERY_DETECT: R211.1(A) ; also on sheet 4 7
CARD2_DETECT: SW401.4 ; also on sheet 8
CONNECT_TO_AV: C288.2(B) R260.1(A) R286.2(B) SW200.1(B1) SW200.2(B2) ; also on sheet 7
CONNECT_TO_AV_CF3: J200.156(ANT_CTL_3) R260.2(B) ; also on sheet 10
CORRECT_INSERTION: J200.39(GND6) ; also on sheet 2
DCDC_SHUTDOWN: SW401.8 ; also on sheet 3
final_GPIO1/I2C1_CLK: J200.1(I2C1_CLK) R227.2(B)
final_GPIO5/I2C1_DATA: J200.66(I2C1_DAT) R225.2(B)
GPIO1/I2C1_CLK: R227.1(A) R242.1(A) R561.1(A) ; also on sheet 4 9 10
GPIO3: J200.64(UIM1_DET) ; also on sheet 8 10
GPIO4: J200.65(UIM2_DET) ; also on sheet 8 10
GPIO5/I2C1_DATA: R225.1(A) R243.1(A) R560.1(A) ; also on sheet 4 9 10
GPIO20/SWD_CLK: CN400.5 J200.102(GPIO36) R425.1(A)
GPIO31/SWD_DIO: CN400.3 J200.103(GPIO37) R427.1(A)
GPIO_IOT0_RESET: R405.1(A) R436.1(A) U404.2(B) ; also on sheet 7
GPIO_IOT1_RESET: R407.1(A) R435.1(A) U402.2(B) ; also on sheet 7 10
GPIO_IOT2_RESET: R406.1(A) R437.1(A) U406.2(B) ; also on sheet 7 10
GPIO_LOWPOWER1: J200.101(GPIO35) ; also on sheet 10
GPIO_LOWPOWER2: J200.100(GPIO34) ; also on sheet 10
GPIO_SCF3_RESET: R212.1(A) R413.1(A) U405.2(B) ; also on sheet 7
GPIOEXP_INT1: R210.1(A) ; also on sheet 7
GPIOEXP_INT2: J200.10(GPIO2) ; also on sheet 7 10
HSIC_DATA: J200.14(HSIC_DATA) ; also on sheet 5
HSIC_STRB: J200.15(HSIC_STRB) ; also on sheet 5
IOT0_GPIO1: J200.109(GPIO42) ; also on sheet 6 8 10
IOT0_GPIO2: J200.105(GPIO33) ; also on sheet 6 10
IOT0_GPIO3: J200.44(GPIO13) ; also on sheet 6 10
IOT0_GPIO4: J200.41(GPIO8) ; also on sheet 6 10
IOT1_GPIO1: C206.2(B) J200.159(GPIO25) ; also on sheet 6 10
IOT1_GPIO2: J200.40(GPIO7) ; also on sheet 6 10
IOT1_GPIO3: J200.104(GPIO32) ; also on sheet 6 10
IOT1_GPIO4: J200.147(GPIO21) ; also on sheet 6 10
IOT2_GPIO1: C205.2(B) J200.148(GPIO22) ; also on sheet 6 10
IOT2_GPIO2: C204.2(B) J200.149(GPIO23) ; also on sheet 6 10
IOT2_GPIO3: C208.2(B) J200.150(GPIO24) ; also on sheet 6 10
IOT2_GPIO4: J200.43(EXT_GPS_LNA_EN) ; also on sheet 6 10
JTAG_RESET: CN401.15 J200.236(RESET)
JTAG_RTCK: CN401.11 J200.242(RTCK)
JTAG_TCK: CN401.9 J200.237(TCK) R421.1(A)
JTAG_TDI: CN401.5 J200.241(TDI) R417.1(A)
JTAG_TDO: CN401.13 J200.238(TDO) R423.1(A)
JTAG_TMS: CN401.7 J200.239(TMS) R419.1(A)
JTAG_TRST: CN401.3 J200.240(TRST) R416.2(B)
LDO_PG: R402.1(A) ; also on sheet 2
LED: D200.1(C) D200.3 J200.106(WWAN_LED_N)
LOWPOWER_RESET: J200.46(GPIO6) R403.1(A) R404.2(B) U401.1(A) ; also on sheet 10
M+: C508.2(B) L512.1(A) L513.1(A) U500.12(COM1)
M-: C508.1(A) L502.1(A) L506.1(A) U500.16(COM2)
MDM_POWER_SW_ON: J200.244(MDM_PWR_SW_ON) SW401.2
MIC+: C503.2(B) C526.2(B) L501.1(A) R501.1(A)
MIC+_SIG: C507.1(A) L501.2(B) U500.13(NC1)
MIC-: C503.1(A) C523.2(B) L504.1(A) R502.2(B)
MIC-_SIG: C510.2(B) L504.2(B) U500.1(NC2)
MIC_N: C502.1(A) J200.20(MIC_N) L505.1(A)
MIC_N_SIG: C509.2(B) L505.2(B) U500.15(NO2)
MIC_P: C502.2(B) J200.19(MIC_P) L503.1(A)
MIC_P_SIG: C505.1(A) L503.2(B) U500.11(NO1)
MICBIAS: C519.2(B) R501.2(B) U501.A5(MICBIAS)
PCM_ANALOG: Q500.3(C) R500.1(A) U500.6(IN3_4) U500.14(IN1_2)
PCM_ANALOG_SELECT: Q500.5(B) R510.1(A) ; also on sheet 7
PCM_CLK: J200.36(PCM_CLK) ; also on sheet 7 10
PCM_CLK_CODEC: U501.D1(BCLK) ; also on sheet 7
PCM_IN: J200.34(PCM_IN) ; also on sheet 7 10
PCM_IN_CODEC: U501.E4(ADCDAT) ; also on sheet 7
PCM_OUT: C201.2(B) J200.33(PCM_OUT) ; also on sheet 7 10
PCM_OUT_CODEC: U501.D3(DACDAT) ; also on sheet 7
PCM_SYNC: J200.35(PCM_SYNC) ; also on sheet 7 10
PCM_SYNC_CODEC: U501.D2(LRCLK) ; also on sheet 7
PPS: J200.42(DR_SYNC) ; also on sheet 6 10
PSHOLD: J200.243(PS_HOLD) R426.1(A)
PWR_IND: J200.152(SAFE_PWR_REMOVE) ; also on sheet 10
PWR_ON: J200.59(PWR_ON_N) SW401.1 ; also on sheet 10
RESET_IN: CN400.9 D400.2 J200.11(RESET_IN_N) R401.2(B) U401.2(B) ; also on sheet 10
RESET_IOT0: R410.2(B) ; also on sheet 6
RESET_IOT1: R409.2(B) ; also on sheet 6
RESET_IOT2: R411.2(B) ; also on sheet 6
RESET_SCF3: R414.2(B) ; also on sheet 10
RF_DIV: D303.2 J200.31(RF_DIV) R300.1(A) R303.1(A)
RF_GPS: C303.1(A) J200.38(RF_GPS)
RF_MAIN: D304.2 J200.49(RF_MAIN) R301.1(A) R302.1(A)
S_PWR_ON: SW401.5 ; also on sheet 10
S_RF_DIV: CN308.1(IN) D315.2 ; also on sheet 10
S_RF_GPS: CN310.1(IN) D316.2 ; also on sheet 10
S_RF_MAIN: CN309.1(IN) D317.2 ; also on sheet 10
SD_CLK: J200.162(SD_CLK) ; also on sheet 7 10
SD_CMD: J200.161(SD_CMD) ; also on sheet 7 10
SD_D0: J200.166(SD_D0) ; also on sheet 7 10
SD_D1: J200.165(SD_D1) ; also on sheet 7 10
SD_D2: J200.164(SD_D2) ; also on sheet 7 10
SD_D3: J200.163(SD_D3) ; also on sheet 7 10
SP+: CN500.4 U500.4(COM3)
SP-: CN500.1 U500.8(COM4)
SPI1_CLK: J200.53(SPI1_CLK) TP221.1(A) ; also on sheet 7
SPI1_MISO: J200.52(SPI1_MISO) TP220.1(A) ; also on sheet 7
SPI1_MOSI: J200.54(SPI1_MOSI) TP222.1(A) ; also on sheet 7
SPI1_MRDY: C202.2(B) J200.51(SPI1_MRDY) TP219.1(A) ; also on sheet 7
SPI2_CLK: J200.92(SPI2_CLK) TP218.1(A) ; also on sheet 6 10
SPI2_MISO: J200.94(SPI2_MISO) TP216.1(A) ; also on sheet 6 10
SPI2_MOSI: J200.93(SPI2_MOSI) TP217.1(A) ; also on sheet 6 10
SPI2_MRDY: J200.95(SPI2_CS0) TP215.1(A) ; also on sheet 6 10
SPK+: C518.2(B) L507.1(A) U501.B2(SPKOUTP)
SPK+_SIG: C511.1(A) L507.2(B) U500.5(NC3)
SPK-: C516.2(B) L509.1(A) U501.B1(SPKOUTN)
SPK-_SIG: C513.1(A) L509.2(B) U500.9(NC4)
SPKP_P_SIG: C512.1(A) L508.2(B) U500.3(NO3)
SPKR_N: C515.2(B) J200.17(SPKR_N) L510.1(A)
SPKR_N_SIG: C514.1(A) L510.2(B) U500.7(NO4)
SPKR_P: C517.2(B) J200.18(SPKR_P) L508.1(A)
SYSTEM_CLK: C237.2(B) R237.2(B) U501.E1(MCLK) ; also on sheet 10
SYSTEM_RESET: R430.1(A) U401.4(Y) U402.1(A) U403.1(A) U404.1(A) U405.1(A) U406.1(A) U1101.3(A) ; also on sheet 5 7 9
SYSTEM_RESET_3V3: R1104.2(B) U1101.4(B) ; also on sheet 5
TP1_BOOT: C203.2(B) CN200.2 J200.47(TP1) SW401.7
UART1_CTS: J200.4(UART1_CTS) ; also on sheet 7 10
UART1_DCD: J200.8(UART1_DCD) ; also on sheet 10
UART1_DSR: J200.9(UART1_DSR) ; also on sheet 10
UART1_DTR: J200.7(UART1_DTR) ; also on sheet 10
UART1_RI: J200.2(UART1_RI) ; also on sheet 10
UART1_RTS: J200.3(UART1_RTS) ; also on sheet 7 10
UART1_RX_HL_WP: J200.6(UART1_RX) ; also on sheet 10
UART1_TX_HL_WP: J200.5(UART1_TX) ; also on sheet 10
UART2_CTS: R222.2(B) ; also on sheet 7 10
UART2_RTS: R220.2(B) ; also on sheet 7 10
UART2_RX: J200.97(UART2_RX) ; also on sheet 7 10
UART2_TX: J200.96(UART2_TX) ; also on sheet 7 10
UART_CTRL: SW401.6 ; also on sheet 10
UIM1_CLK: J200.27(UIM1_CLK) ; also on sheet 8
UIM1_DATA: J200.28(UIM1_DAT) ; also on sheet 8
UIM1_RESET: J200.29(UIM1_RST) ; also on sheet 8
UIM1_VCC: J200.26(UIM1_VCC) ; also on sheet 8
UIM2_CLK: J200.58(UIM2_CLK) ; also on sheet 8
UIM2_DAT: J200.56(UIM2_DAT) ; also on sheet 8
UIM2_RST: J200.57(UIM2_RST) ; also on sheet 8
UIM2_VCC: J200.55(UIM2_VCC) ; also on sheet 8
USB7_CN_D+: CN327.3(D+) D330.2(D+) D347.2(A2)
USB7_CN_D-: CN327.2(D-) D330.1(D-) D347.1(A1)
USB7_D+: D347.3(B2) ; also on sheet 5
USB7_D-: D347.4(B1) ; also on sheet 5
USB_CN_D+: CN311.3(D+) D311.1(D-) D326.2(A2) TP300.1(A)
USB_CN_D-: CN311.2(D-) D311.2(D+) D326.1(A1) TP301.1(A)
USB_D+: D326.3(B2) J200.13(USB_DP)
USB_D-: D326.4(B1) J200.12(USB_DN)
USB_ID: CN311.4(ID) D311.3(ID) J200.91(USB_ID) R389.1(A) U300.2(A)
USB_VBUS: C338.2(B) CN311.1(VBUS) D310.1(C) D311.6(VBUS) ; also on sheet 4
USBD+_ARD: R317.2(B) ; also on sheet 1
USBD+_ARD_CN: CN330.3(D+) D334.2(D+) R317.1(A)
USBD-_ARD: R315.2(B) ; also on sheet 1
USBD-_ARD_CN: CN330.2(D-) D334.1(D-) R315.1(A)
VGPIO: C408.1(A) CN401.1 CN401.2 R229.2(B) R242.2(B) R243.2(B) R389.2(B) R417.2(B) R419.2(B) R421.2(B) R423.2(B) R450.1(A) U300.6(VCC) ; also on sheet 4 6
W_DISABLE_N: C207.2(B) J200.151(W_DISABLE_N) SW401.3 ; also on sheet 9 10
WAKE_ON_WWAN: J200.110(WAKE_ON_WWAN) ; also on sheet 10
WP2ARDUINO_RESET: U403.4(Y) ; also on sheet 1
$1N33094: J200.98(UART2_RTS) R220.1(A)
$1N33164: J200.99(UART2_CTS) R222.1(A)
$1N33902: J200.23(SLEEP_CLK) R236.1(A)
$1N33904: J200.22(SYSTEM_CLK) R237.1(A)
$1N34272: R200.2(B) TP210.1(A)
$1N34305: R201.2(B) TP211.1(A)
$1N34338: R202.2(B) TP212.1(A)
$1N34371: R203.2(B) TP213.1(A)
$1N34420: J200.45(VGPIO) R229.1(A)
$2N8360: C346.1(A) C347.1(A) CN320.2 R309.1(A)
$2N13586: CN302.1(IN) R302.2(B)
$2N13651: CN305.1(IN) R305.2(B)
$2N13654: CN303.1(IN) R303.2(B)
$2N13656: CN307.1(IN) R301.2(B)
$2N13689: CN304.1(IN) R300.2(B)
$2N13725: CN306.1(IN) R304.2(B)
$2N15119: D310.2(A) U301.3(VOUT)
$2N15120: R325.2(B) U301.1(ISET)
$2N15121: R339.2(B) U300.4(Y) U301.6(ON)
$2N15122: R318.2(B) U301.4(FLAGB)
$2N33665: C303.2(B) D309.2 L300.2(B) R304.1(A) R305.1(A)
$2N33741: CN330.4(ID) D334.3(ID)
$2N33844: C1585.2(B) L300.1(A) R320.2(B) R321.2(B) R322.2(B)
$2N33955: CN320.1 R306.2(B) R307.2(B) R308.2(B)
$3N15432: R429.1(A) SW401.14
$3N15434: R418.1(A) SW401.15
$3N16442: R426.2(B) R450.2(B)
$3N17490: R422.1(A) SW401.12
$3N17576: R424.2(B) SW401.11
$3N17828: R409.1(A) U402.4(Y)
$3N17862: R410.1(A) U404.4(Y)
$3N17896: R411.1(A) U406.4(Y)
$3N18206: C400.2(B) U400.5(CD)
$3N18300: R400.1(A) U400.2(IN)
$3N18457: R415.1(A) SW401.16
$3N18467: R420.2(B) SW401.10
$3N18714: C405.2(B) R401.1(A) R402.2(B) R408.1(A) SW400.2(B) U400.1(~{RESET})
$15N7473: C506.2(B) CN500.5 L502.2(B) L512.2(B) R520.1(A)
$15N7474: C530.2(B) CN500.6 L506.2(B) L513.2(B) R505.1(A)
$15N10265: TP550.1(A) U501.A2(LINEOUT)
$15N10266: C524.2(B) C525.2(B) R504.2(B) U501.A1(SPKVDD)
$15N10273: C526.1(A) U501.B4(IN1/DMICDAT)
$15N10274: C523.1(A) U501.B3(AUX)
$15N10275: R503.2(B) U501.C1(CIFMODE)
$15N10282: C528.2(B) U501.A4(LDOVOUT)
$15N10283: C527.2(B) U501.A3(VMIDC)
$15N11316: C500.2(B) C501.2(B) L500.1(A) U500.10(V+)
$15N11890: R560.2(B) U501.C3(SDA)
$15N11892: R561.2(B) U501.C4(SCLK)
N1301698: R287.1(A) SW200.3(A1) SW200.4(A2)
N1304862: D200.2(A) R214.2(B)
N1582982: R414.1(A) U405.4(Y)
N1587788: C521.2(B) C522.2(B) L511.1(A) R504.1(A) U501.B5(LDOVDD)

Not connected (* = marked no-connect by the designer): U401 5*; U402 5*; U403 5*; U404 5*; U405 5*; U406 5*

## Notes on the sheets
sheet 11
- Audio Source Selection
- Share footprint
- MIC_OMTP
- MIC_CTIA
- MIC_CTIA
- MIC_OMTP
- Share footprint
- L = ANALOG
- H = PCM
- Audio Codec
- Changed original power config
- I2C address 00011010b
- I2C address 1Ah
sheet 12
- OPHW Platform RESET
- CONTRL SWITCH
- RESET if LDO output to CF3 is not valid
- SYSTEM RESET
- uC DEBUG
- R403 = ON , R404 = DNI --> System_reset is High during startup and when LowPowerReset = HiZ
- R403 = DNI , R404 = ON --> System_reset is Low during startup and when LowPowerReset = HiZ
- (SWD_CLK)
- (SWD_DAT)
- RESET_IOT1
- JTAG
- RESET_IOT0
- RESET_IOT2
- RESET_Secondary CF3
sheet 13
- MAIN CF3 Socket
- USB OTG
- Main Antenna
- SECONDARY CF3 Socket
- USB CONN
- Diversity
- Main Antenna
- Replace with FPF2163 if Autorestart is required
- Diversity
- Input is made high for system stability
- GPS
- Active Antenna Supply
- GPS
- USB Arduino Programming
- USB HOST
- VBACKUP/DISCHARGE
- RTC Backup Battery
sheet 14
- INNER RING
- GROUND SLUG
- JTAG
- POST TERMINAL STRIP
- OUTER RING
- Mounting Holes
- Mounting holes can be disconnected from GND
sheet 15
- MangoH Green Platform
- Project Variants
- SHEET 1 TABLE OF CONTENTS
- 1600643
- SHEET 2 CONNECTORS
- SHEET 3 RF, VBACKUP,USB
- DNI
- N
- UFL_M_RF
- Y
- SHEET 4 RESET,JTAG,uC prog,control
- SMA_RF
- N
- SHEET 5 AUDIO (ANALOG & PCM)
- MIC_OMTP
- N
- SHEET 6 CONNECTORS & Headers
- MIC_CTIA
- Y
- SHEET 7 UART, LEDs, ADC,Level Shifter
- Variants description
- SHEET 8 UIMs & SD CARD
- DNI = Do Not Install
- UFL_M_RF = Add U.FL conn. on Main CF3 (do not define SMA_RF)
- SHEET 9  GPIO, SPI,UART, SDIO,PCM Expanders
- SMA_RF = Add SMA conn. on Main CF3 (do not define UFL_M_RF)
- MIC_OMTP = OMTP headphones config (do not define MIC_CTIA)
- MIC_CTIA = CTIA/AHJ headphones config (do not define MIC_OMTP)
- SHEET 10 IOT connectors,Sensors
- SHEET 11 USB, Ethernet expansion
- I2C address list
- SHEET 12 PSU Front end, 3.7V DCDC
- 08h = 3503 USB hub
- 3Eh = I/O expander 1
- 3Fh = I/O expander 2
- SHEET 13 Battery Charger
- 55h = Battery gauge
- 6Ah = Accelerometer sensor
- SHEET 14  5V boost, 3V3 buck, 1V8 Buck
- 6Bh = Buck+batt charger
- 70h = I/O expander 3
- SHEET 15  Arduino connection
- 71h = I2C Hub
- REFERENCE
- 1600643 PCA, MANGOH
- 1401063 PCB, MANGOH
